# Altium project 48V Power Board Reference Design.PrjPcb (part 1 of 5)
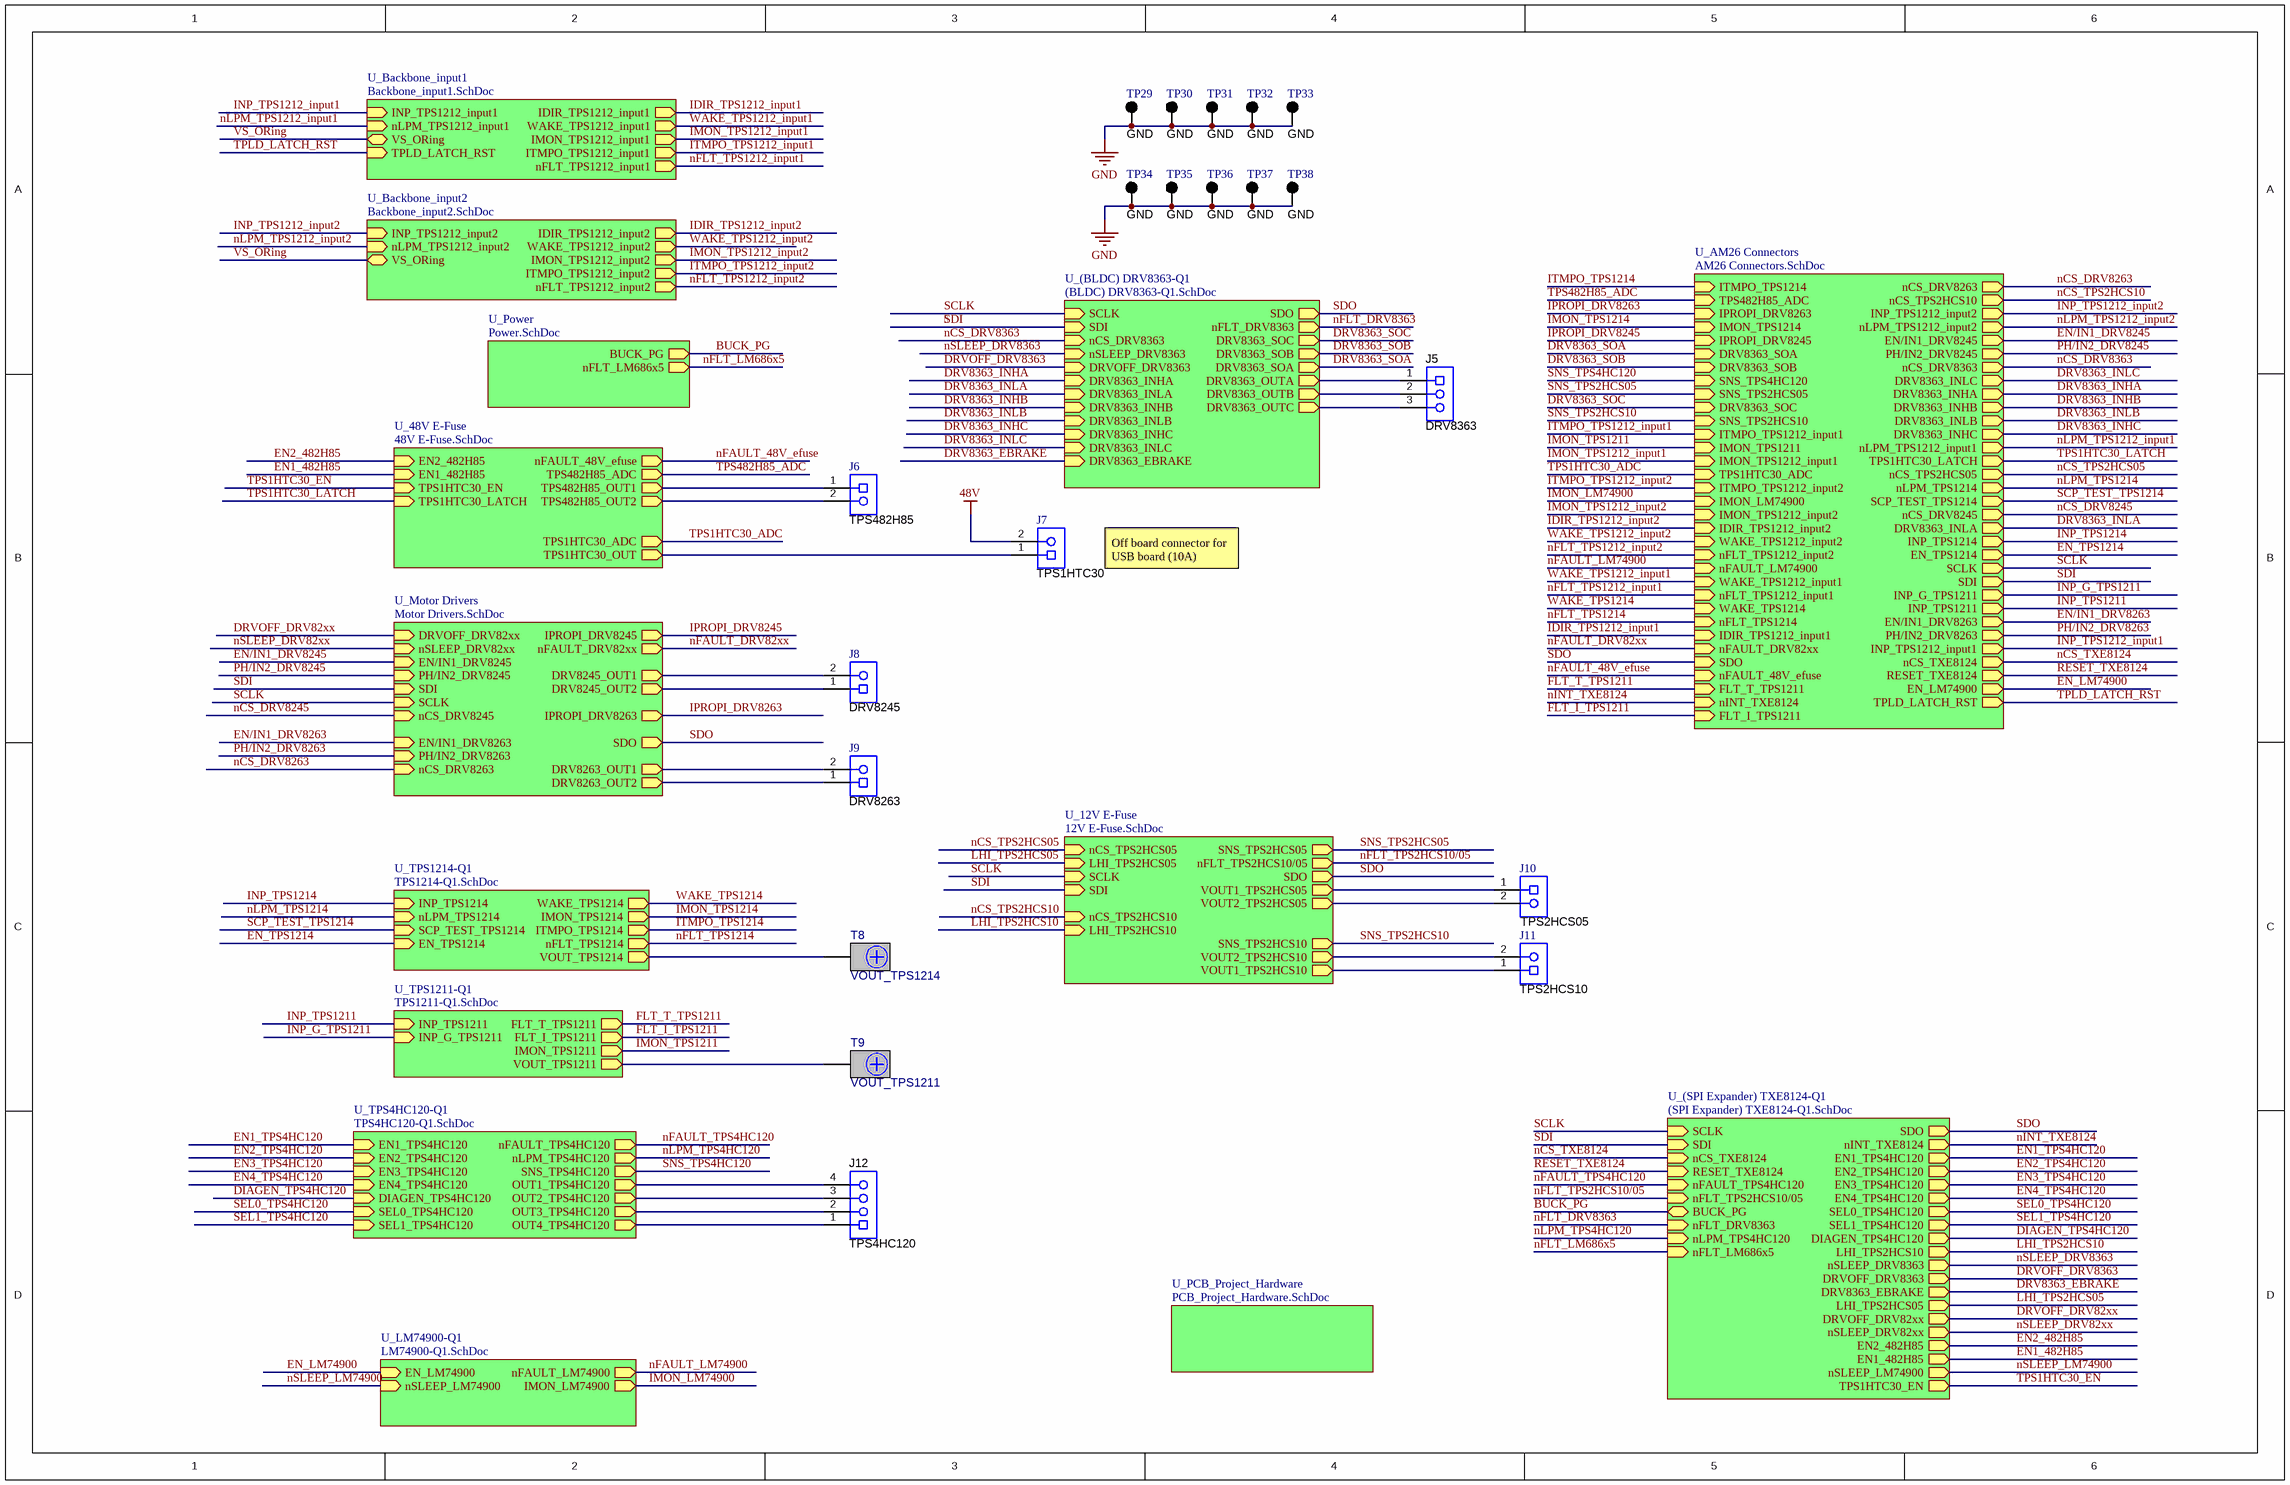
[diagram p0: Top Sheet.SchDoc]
CopyrightYear: 2025; PCB_Layout: LDN/Eagle Circuits; PCB_Rev: E3; PRJ_Customer: Public Release; PRJ_Engineer: Miguel Robertson; PRJ_Number: TIDA-020094; PRJ_Title: 48V Power Board Reference Design; SCH_Rev: E2; TechSupport: http://www.ti.com/support; TID: N/A
15 sheets, 737 parts. Net scope: hierarchical (ports join the sheet entries above them; power ports are global).
Board file: PCB_Project.PcbDoc
Sheets:
  Top Sheet.SchDoc
    U_LM74900-Q1 = LM74900-Q1.SchDoc
    U_TPS1211-Q1 = TPS1211-Q1.SchDoc
    U_TPS4HC120-Q1 = TPS4HC120-Q1.SchDoc
    U_TPS1214-Q1 = TPS1214-Q1.SchDoc
    U_PCB_Project_Hardware = PCB_Project_Hardware.SchDoc
    U_(BLDC) DRV8363-Q1 = (BLDC) DRV8363-Q1.SchDoc
    U_Motor Drivers = Motor Drivers.SchDoc
    U_12V E-Fuse = 12V E-Fuse.SchDoc
    U_Backbone_input2 = Backbone_input2.SchDoc
    U_Power = Power.SchDoc
    U_(SPI Expander) TXE8124-Q1 = (SPI Expander) TXE8124-Q1.SchDoc
    U_AM26 Connectors = AM26 Connectors.SchDoc
    U_Backbone_input1 = Backbone_input1.SchDoc
    U_48V E-Fuse = 48V E-Fuse.SchDoc

## Sheet Top Sheet.SchDoc
size 431 x 279 mm; DocumentNumber: 2; SheetNumber: 1; SheetTotal: 15

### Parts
J5  DRV8363  [Phoenix_1904150]
J6  TPS482H85  [PhoenixContact_1715721]
J7  TPS1HTC30  [PhoenixContact_1715721]
J8  DRV8245  [Phoenix_1902547]
J9  DRV8263  [Phoenix_1902547]
J10  TPS2HCS05  [Phoenix_1902547]
J11  TPS2HCS10  [PhoenixContact_1715721]
J12  TPS4HC120  [Phoenix_1715048]
T8  VOUT_TPS1214  [Panduit_CXS70-14-C]
T9  VOUT_TPS1211  [Panduit_CXS70-14-C]
TP29  GND  [Keystone5011]
TP30  GND  [Keystone5011]
TP31  GND  [Keystone5011]
TP32  GND  [Keystone5011]
TP33  GND  [Keystone5011]
TP34  GND  [Keystone5011]
TP35  GND  [Keystone5011]
TP36  GND  [Keystone5011]
TP37  GND  [Keystone5011]
TP38  GND  [Keystone5011]

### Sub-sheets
U_12V E-Fuse = 12V E-Fuse.SchDoc: VOUT1_TPS2HCS10 (out), VOUT2_TPS2HCS10 (out), LHI_TPS2HCS10 (in), nFLT_TPS2HCS10/05 (out), nCS_TPS2HCS10 (in), nCS_TPS2HCS05 (in), VOUT1_TPS2HCS05 (out), VOUT2_TPS2HCS05 (out), LHI_TPS2HCS05 (in), SCLK (in), SDI (in), SDO (out), SNS_TPS2HCS10 (out), SNS_TPS2HCS05 (out)
U_48V E-Fuse = 48V E-Fuse.SchDoc: EN2_482H85 (in), EN1_482H85 (in), TPS1HTC30_EN (in), TPS1HTC30_LATCH (in), nFAULT_48V_efuse (out), TPS1HTC30_OUT (out), TPS482H85_OUT1 (out), TPS482H85_OUT2 (out), TPS482H85_ADC (out), TPS1HTC30_ADC (out)
U_(BLDC) DRV8363-Q1 = (BLDC) DRV8363-Q1.SchDoc: SCLK (in), SDI (in), nCS_DRV8363 (in), SDO (out), nSLEEP_DRV8363 (in), DRVOFF_DRV8363 (in), nFLT_DRV8363 (out), DRV8363_INHA (in), DRV8363_INLA (in), DRV8363_INHB (in), DRV8363_INLB (in), DRV8363_INHC (in), DRV8363_INLC (in), DRV8363_SOC (out), DRV8363_SOB (out), DRV8363_SOA (out), DRV8363_EBRAKE (in), DRV8363_OUTA (out), DRV8363_OUTB (out), DRV8363_OUTC (out)
U_(SPI Expander) TXE8124-Q1 = (SPI Expander) TXE8124-Q1.SchDoc: SCLK (in), SDI (in), SDO (out), nCS_TXE8124 (in), nINT_TXE8124 (out), RESET_TXE8124 (in), EN1_TPS4HC120 (out), EN2_TPS4HC120 (out), EN3_TPS4HC120 (out), EN4_TPS4HC120 (out), SEL0_TPS4HC120 (out), SEL1_TPS4HC120 (out), nFAULT_TPS4HC120 (in), DIAGEN_TPS4HC120 (out), LHI_TPS2HCS10 (out), nFLT_TPS2HCS10/05 (in), nSLEEP_DRV8363 (out), DRVOFF_DRV8363 (out), BUCK_PG (bidir), DRV8363_EBRAKE (out), nFLT_DRV8363 (in), LHI_TPS2HCS05 (out), nLPM_TPS4HC120 (in), DRVOFF_DRV82xx (out), nSLEEP_DRV82xx (out), EN2_482H85 (out), EN1_482H85 (out), nFLT_LM686x5 (in), nSLEEP_LM74900 (out), TPS1HTC30_EN (out)
U_AM26 Connectors = AM26 Connectors.SchDoc: ITMPO_TPS1214 (in), TPS482H85_ADC (in), IPROPI_DRV8263 (in), IMON_TPS1214 (in), nCS_DRV8263 (out), IPROPI_DRV8245 (in), DRV8363_SOA (in), DRV8363_SOB (in), SNS_TPS4HC120 (in), SNS_TPS2HCS05 (in), DRV8363_SOC (in), SNS_TPS2HCS10 (in), ITMPO_TPS1212_input1 (in), IMON_TPS1211 (in), IMON_TPS1212_input1 (in), TPS1HTC30_ADC (in), ITMPO_TPS1212_input2 (in), IMON_LM74900 (in), IMON_TPS1212_input2 (in), nCS_TPS2HCS10 (out), INP_TPS1212_input2 (out), nLPM_TPS1212_input2 (out), IDIR_TPS1212_input2 (in), WAKE_TPS1212_input2 (in), nFLT_TPS1212_input2 (in), EN/IN1_DRV8245 (out), PH/IN2_DRV8245 (out), nFAULT_LM74900 (in), nCS_DRV8363 (out), DRV8363_INLC (out), DRV8363_INHA (out), DRV8363_INHB (out), DRV8363_INLB (out), DRV8363_INHC (out), WAKE_TPS1212_input1 (in), nLPM_TPS1212_input1 (out), TPS1HTC30_LATCH (out), nFLT_TPS1212_input1 (in), nCS_TPS2HCS05 (out), nLPM_TPS1214 (out), WAKE_TPS1214 (in), nFLT_TPS1214 (in), SCP_TEST_TPS1214 (out), nCS_DRV8245 (out), IDIR_TPS1212_input1 (in), nFAULT_DRV82xx (in), SDO (in), DRV8363_INLA (out), INP_TPS1214 (out), EN_TPS1214 (out), SCLK (out), SDI (out), INP_G_TPS1211 (out), INP_TPS1211 (out), EN/IN1_DRV8263 (out), PH/IN2_DRV8263 (out), nFAULT_48V_efuse (in), INP_TPS1212_input1 (out), FLT_T_TPS1211 (in), nINT_TXE8124 (in), nCS_TXE8124 (out), RESET_TXE8124 (out), FLT_I_TPS1211 (in), EN_LM74900 (out), TPLD_LATCH_RST (out)
U_Backbone_input1 = Backbone_input1.SchDoc: INP_TPS1212_input1 (in), nLPM_TPS1212_input1 (in), IDIR_TPS1212_input1 (out), WAKE_TPS1212_input1 (out), IMON_TPS1212_input1 (out), ITMPO_TPS1212_input1 (out), nFLT_TPS1212_input1 (out), VS_ORing (bidir), TPLD_LATCH_RST (in)
U_Backbone_input2 = Backbone_input2.SchDoc: INP_TPS1212_input2 (in), nLPM_TPS1212_input2 (in), IDIR_TPS1212_input2 (out), WAKE_TPS1212_input2 (out), IMON_TPS1212_input2 (out), ITMPO_TPS1212_input2 (out), nFLT_TPS1212_input2 (out), VS_ORing (bidir)
U_LM74900-Q1 = LM74900-Q1.SchDoc: nFAULT_LM74900 (out), EN_LM74900 (in), nSLEEP_LM74900 (in), IMON_LM74900 (out)
U_Motor Drivers = Motor Drivers.SchDoc: DRVOFF_DRV82xx (in), nSLEEP_DRV82xx (in), EN/IN1_DRV8245 (in), PH/IN2_DRV8245 (in), SDI (in), SCLK (in), nFAULT_DRV82xx (out), nCS_DRV8245 (in), SDO (out), EN/IN1_DRV8263 (in), PH/IN2_DRV8263 (in), nCS_DRV8263 (in), DRV8245_OUT1 (out), DRV8245_OUT2 (out), DRV8263_OUT1 (out), DRV8263_OUT2 (out), IPROPI_DRV8263 (out), IPROPI_DRV8245 (out)
U_PCB_Project_Hardware = PCB_Project_Hardware.SchDoc: no entries
U_Power = Power.SchDoc: BUCK_PG (out), nFLT_LM686x5 (out)
U_TPS4HC120-Q1 = TPS4HC120-Q1.SchDoc: EN1_TPS4HC120 (in), EN2_TPS4HC120 (in), EN3_TPS4HC120 (in), EN4_TPS4HC120 (in), DIAGEN_TPS4HC120 (in), SEL0_TPS4HC120 (in), SEL1_TPS4HC120 (in), nFAULT_TPS4HC120 (out), nLPM_TPS4HC120 (out), SNS_TPS4HC120 (out), OUT1_TPS4HC120 (out), OUT2_TPS4HC120 (out), OUT3_TPS4HC120 (out), OUT4_TPS4HC120 (out)
U_TPS1211-Q1 = TPS1211-Q1.SchDoc: INP_TPS1211 (in), INP_G_TPS1211 (in), FLT_T_TPS1211 (out), FLT_I_TPS1211 (out), IMON_TPS1211 (out), VOUT_TPS1211 (out)
U_TPS1214-Q1 = TPS1214-Q1.SchDoc: INP_TPS1214 (in), nLPM_TPS1214 (in), SCP_TEST_TPS1214 (in), WAKE_TPS1214 (out), VOUT_TPS1214 (out), IMON_TPS1214 (out), ITMPO_TPS1214 (out), nFLT_TPS1214 (out), EN_TPS1214 (in)

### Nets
48V: J7.2
GND: TP29.1 TP30.1 TP31.1 TP32.1 TP33.1 TP34.1 TP35.1 TP36.1 TP37.1 TP38.1
: sheet U_(BLDC) DRV8363-Q1/SDI, sheet U_Motor Drivers/SDI, sheet U_12V E-Fuse/SDI, sheet U_(SPI Expander) TXE8124-Q1/SDI, sheet U_AM26 Connectors/SDI  [also labelled SDI]
BUCK_PG: sheet U_Power/BUCK_PG, sheet U_(SPI Expander) TXE8124-Q1/BUCK_PG
DIAGEN_TPS4HC120: sheet U_TPS4HC120-Q1/DIAGEN_TPS4HC120, sheet U_(SPI Expander) TXE8124-Q1/DIAGEN_TPS4HC120
DRV8245_OUT1: J8.2 ; sheet U_Motor Drivers/DRV8245_OUT1
DRV8245_OUT2: J8.1 ; sheet U_Motor Drivers/DRV8245_OUT2
DRV8263_OUT1: J9.2 ; sheet U_Motor Drivers/DRV8263_OUT1
DRV8263_OUT2: J9.1 ; sheet U_Motor Drivers/DRV8263_OUT2
DRV8363_EBRAKE: sheet U_(BLDC) DRV8363-Q1/DRV8363_EBRAKE, sheet U_(SPI Expander) TXE8124-Q1/DRV8363_EBRAKE
DRV8363_INHA: sheet U_(BLDC) DRV8363-Q1/DRV8363_INHA, sheet U_AM26 Connectors/DRV8363_INHA
DRV8363_INHB: sheet U_(BLDC) DRV8363-Q1/DRV8363_INHB, sheet U_AM26 Connectors/DRV8363_INHB
DRV8363_INHC: sheet U_(BLDC) DRV8363-Q1/DRV8363_INHC, sheet U_AM26 Connectors/DRV8363_INHC
DRV8363_INLA: sheet U_(BLDC) DRV8363-Q1/DRV8363_INLA, sheet U_AM26 Connectors/DRV8363_INLA
DRV8363_INLB: sheet U_(BLDC) DRV8363-Q1/DRV8363_INLB, sheet U_AM26 Connectors/DRV8363_INLB
DRV8363_INLC: sheet U_(BLDC) DRV8363-Q1/DRV8363_INLC, sheet U_AM26 Connectors/DRV8363_INLC
DRV8363_OUTA: J5.1 ; sheet U_(BLDC) DRV8363-Q1/DRV8363_OUTA
DRV8363_OUTB: J5.2 ; sheet U_(BLDC) DRV8363-Q1/DRV8363_OUTB
DRV8363_OUTC: J5.3 ; sheet U_(BLDC) DRV8363-Q1/DRV8363_OUTC
DRV8363_SOA: sheet U_(BLDC) DRV8363-Q1/DRV8363_SOA, sheet U_AM26 Connectors/DRV8363_SOA
DRV8363_SOB: sheet U_(BLDC) DRV8363-Q1/DRV8363_SOB, sheet U_AM26 Connectors/DRV8363_SOB
DRV8363_SOC: sheet U_(BLDC) DRV8363-Q1/DRV8363_SOC, sheet U_AM26 Connectors/DRV8363_SOC
DRVOFF_DRV82xx: sheet U_Motor Drivers/DRVOFF_DRV82xx, sheet U_(SPI Expander) TXE8124-Q1/DRVOFF_DRV82xx
DRVOFF_DRV8363: sheet U_(BLDC) DRV8363-Q1/DRVOFF_DRV8363, sheet U_(SPI Expander) TXE8124-Q1/DRVOFF_DRV8363
EN1_482H85: sheet U_(SPI Expander) TXE8124-Q1/EN1_482H85, sheet U_48V E-Fuse/EN1_482H85
EN1_TPS4HC120: sheet U_TPS4HC120-Q1/EN1_TPS4HC120, sheet U_(SPI Expander) TXE8124-Q1/EN1_TPS4HC120
EN2_482H85: sheet U_(SPI Expander) TXE8124-Q1/EN2_482H85, sheet U_48V E-Fuse/EN2_482H85
EN2_TPS4HC120: sheet U_TPS4HC120-Q1/EN2_TPS4HC120, sheet U_(SPI Expander) TXE8124-Q1/EN2_TPS4HC120
EN3_TPS4HC120: sheet U_TPS4HC120-Q1/EN3_TPS4HC120, sheet U_(SPI Expander) TXE8124-Q1/EN3_TPS4HC120
EN4_TPS4HC120: sheet U_TPS4HC120-Q1/EN4_TPS4HC120, sheet U_(SPI Expander) TXE8124-Q1/EN4_TPS4HC120
EN/IN1_DRV8245: sheet U_Motor Drivers/EN/IN1_DRV8245, sheet U_AM26 Connectors/EN/IN1_DRV8245
EN/IN1_DRV8263: sheet U_Motor Drivers/EN/IN1_DRV8263, sheet U_AM26 Connectors/EN/IN1_DRV8263
EN_LM74900: sheet U_LM74900-Q1/EN_LM74900, sheet U_AM26 Connectors/EN_LM74900
EN_TPS1214: sheet U_TPS1214-Q1/EN_TPS1214, sheet U_AM26 Connectors/EN_TPS1214
FLT_I_TPS1211: sheet U_TPS1211-Q1/FLT_I_TPS1211, sheet U_AM26 Connectors/FLT_I_TPS1211
FLT_T_TPS1211: sheet U_TPS1211-Q1/FLT_T_TPS1211, sheet U_AM26 Connectors/FLT_T_TPS1211
IDIR_TPS1212_input1: sheet U_AM26 Connectors/IDIR_TPS1212_input1, sheet U_Backbone_input1/IDIR_TPS1212_input1
IDIR_TPS1212_input2: sheet U_Backbone_input2/IDIR_TPS1212_input2, sheet U_AM26 Connectors/IDIR_TPS1212_input2
IMON_LM74900: sheet U_LM74900-Q1/IMON_LM74900, sheet U_AM26 Connectors/IMON_LM74900
IMON_TPS1211: sheet U_TPS1211-Q1/IMON_TPS1211, sheet U_AM26 Connectors/IMON_TPS1211
IMON_TPS1212_input1: sheet U_AM26 Connectors/IMON_TPS1212_input1, sheet U_Backbone_input1/IMON_TPS1212_input1
IMON_TPS1212_input2: sheet U_Backbone_input2/IMON_TPS1212_input2, sheet U_AM26 Connectors/IMON_TPS1212_input2
IMON_TPS1214: sheet U_TPS1214-Q1/IMON_TPS1214, sheet U_AM26 Connectors/IMON_TPS1214
INP_G_TPS1211: sheet U_TPS1211-Q1/INP_G_TPS1211, sheet U_AM26 Connectors/INP_G_TPS1211
INP_TPS1211: sheet U_TPS1211-Q1/INP_TPS1211, sheet U_AM26 Connectors/INP_TPS1211
INP_TPS1212_input1: sheet U_AM26 Connectors/INP_TPS1212_input1, sheet U_Backbone_input1/INP_TPS1212_input1
INP_TPS1212_input2: sheet U_Backbone_input2/INP_TPS1212_input2, sheet U_AM26 Connectors/INP_TPS1212_input2
INP_TPS1214: sheet U_TPS1214-Q1/INP_TPS1214, sheet U_AM26 Connectors/INP_TPS1214
IPROPI_DRV8245: sheet U_Motor Drivers/IPROPI_DRV8245, sheet U_AM26 Connectors/IPROPI_DRV8245
IPROPI_DRV8263: sheet U_Motor Drivers/IPROPI_DRV8263, sheet U_AM26 Connectors/IPROPI_DRV8263
ITMPO_TPS1212_input1: sheet U_AM26 Connectors/ITMPO_TPS1212_input1, sheet U_Backbone_input1/ITMPO_TPS1212_input1
ITMPO_TPS1212_input2: sheet U_Backbone_input2/ITMPO_TPS1212_input2, sheet U_AM26 Connectors/ITMPO_TPS1212_input2
ITMPO_TPS1214: sheet U_TPS1214-Q1/ITMPO_TPS1214, sheet U_AM26 Connectors/ITMPO_TPS1214
LHI_TPS2HCS05: sheet U_12V E-Fuse/LHI_TPS2HCS05, sheet U_(SPI Expander) TXE8124-Q1/LHI_TPS2HCS05
LHI_TPS2HCS10: sheet U_12V E-Fuse/LHI_TPS2HCS10, sheet U_(SPI Expander) TXE8124-Q1/LHI_TPS2HCS10
nCS_DRV8245: sheet U_Motor Drivers/nCS_DRV8245, sheet U_AM26 Connectors/nCS_DRV8245
nCS_DRV8263: sheet U_Motor Drivers/nCS_DRV8263, sheet U_AM26 Connectors/nCS_DRV8263
nCS_DRV8363: sheet U_(BLDC) DRV8363-Q1/nCS_DRV8363, sheet U_AM26 Connectors/nCS_DRV8363
nCS_TPS2HCS05: sheet U_12V E-Fuse/nCS_TPS2HCS05, sheet U_AM26 Connectors/nCS_TPS2HCS05
nCS_TPS2HCS10: sheet U_12V E-Fuse/nCS_TPS2HCS10, sheet U_AM26 Connectors/nCS_TPS2HCS10
nCS_TXE8124: sheet U_(SPI Expander) TXE8124-Q1/nCS_TXE8124, sheet U_AM26 Connectors/nCS_TXE8124
nFAULT_48V_efuse: sheet U_AM26 Connectors/nFAULT_48V_efuse, sheet U_48V E-Fuse/nFAULT_48V_efuse
nFAULT_DRV82xx: sheet U_Motor Drivers/nFAULT_DRV82xx, sheet U_AM26 Connectors/nFAULT_DRV82xx
nFAULT_LM74900: sheet U_LM74900-Q1/nFAULT_LM74900, sheet U_AM26 Connectors/nFAULT_LM74900
nFAULT_TPS4HC120: sheet U_TPS4HC120-Q1/nFAULT_TPS4HC120, sheet U_(SPI Expander) TXE8124-Q1/nFAULT_TPS4HC120
nFLT_DRV8363: sheet U_(BLDC) DRV8363-Q1/nFLT_DRV8363, sheet U_(SPI Expander) TXE8124-Q1/nFLT_DRV8363  [project net nFAULT_DRV8363]
nFLT_LM686x5: sheet U_Power/nFLT_LM686x5, sheet U_(SPI Expander) TXE8124-Q1/nFLT_LM686x5
nFLT_TPS2HCS10/05: sheet U_12V E-Fuse/nFLT_TPS2HCS10/05, sheet U_(SPI Expander) TXE8124-Q1/nFLT_TPS2HCS10/05
nFLT_TPS1212_input1: sheet U_AM26 Connectors/nFLT_TPS1212_input1, sheet U_Backbone_input1/nFLT_TPS1212_input1
nFLT_TPS1212_input2: sheet U_Backbone_input2/nFLT_TPS1212_input2, sheet U_AM26 Connectors/nFLT_TPS1212_input2
nFLT_TPS1214: sheet U_TPS1214-Q1/nFLT_TPS1214, sheet U_AM26 Connectors/nFLT_TPS1214  [project net nFAULT_1214]
nINT_TXE8124: sheet U_(SPI Expander) TXE8124-Q1/nINT_TXE8124, sheet U_AM26 Connectors/nINT_TXE8124
nLPM_TPS4HC120: sheet U_TPS4HC120-Q1/nLPM_TPS4HC120, sheet U_(SPI Expander) TXE8124-Q1/nLPM_TPS4HC120
nLPM_TPS1212_input1: sheet U_AM26 Connectors/nLPM_TPS1212_input1, sheet U_Backbone_input1/nLPM_TPS1212_input1
nLPM_TPS1212_input2: sheet U_Backbone_input2/nLPM_TPS1212_input2, sheet U_AM26 Connectors/nLPM_TPS1212_input2
nLPM_TPS1214: sheet U_TPS1214-Q1/nLPM_TPS1214, sheet U_AM26 Connectors/nLPM_TPS1214
nSLEEP_DRV82xx: sheet U_Motor Drivers/nSLEEP_DRV82xx, sheet U_(SPI Expander) TXE8124-Q1/nSLEEP_DRV82xx
nSLEEP_DRV8363: sheet U_(BLDC) DRV8363-Q1/nSLEEP_DRV8363, sheet U_(SPI Expander) TXE8124-Q1/nSLEEP_DRV8363
nSLEEP_LM74900: sheet U_LM74900-Q1/nSLEEP_LM74900, sheet U_(SPI Expander) TXE8124-Q1/nSLEEP_LM74900
OUT1_TPS4HC120: J12.4 ; sheet U_TPS4HC120-Q1/OUT1_TPS4HC120
OUT2_TPS4HC120: J12.3 ; sheet U_TPS4HC120-Q1/OUT2_TPS4HC120
OUT3_TPS4HC120: J12.2 ; sheet U_TPS4HC120-Q1/OUT3_TPS4HC120
OUT4_TPS4HC120: J12.1 ; sheet U_TPS4HC120-Q1/OUT4_TPS4HC120
PH/IN2_DRV8245: sheet U_Motor Drivers/PH/IN2_DRV8245, sheet U_AM26 Connectors/PH/IN2_DRV8245
PH/IN2_DRV8263: sheet U_Motor Drivers/PH/IN2_DRV8263, sheet U_AM26 Connectors/PH/IN2_DRV8263
RESET_TXE8124: sheet U_(SPI Expander) TXE8124-Q1/RESET_TXE8124, sheet U_AM26 Connectors/RESET_TXE8124
SCLK: sheet U_(BLDC) DRV8363-Q1/SCLK, sheet U_Motor Drivers/SCLK, sheet U_12V E-Fuse/SCLK, sheet U_(SPI Expander) TXE8124-Q1/SCLK, sheet U_AM26 Connectors/SCLK
SCP_TEST_TPS1214: sheet U_TPS1214-Q1/SCP_TEST_TPS1214, sheet U_AM26 Connectors/SCP_TEST_TPS1214
SDO: sheet U_(BLDC) DRV8363-Q1/SDO, sheet U_Motor Drivers/SDO, sheet U_12V E-Fuse/SDO, sheet U_(SPI Expander) TXE8124-Q1/SDO, sheet U_AM26 Connectors/SDO
SEL0_TPS4HC120: sheet U_TPS4HC120-Q1/SEL0_TPS4HC120, sheet U_(SPI Expander) TXE8124-Q1/SEL0_TPS4HC120
SEL1_TPS4HC120: sheet U_TPS4HC120-Q1/SEL1_TPS4HC120, sheet U_(SPI Expander) TXE8124-Q1/SEL1_TPS4HC120
SNS_TPS2HCS05: sheet U_12V E-Fuse/SNS_TPS2HCS05, sheet U_AM26 Connectors/SNS_TPS2HCS05
SNS_TPS2HCS10: sheet U_12V E-Fuse/SNS_TPS2HCS10, sheet U_AM26 Connectors/SNS_TPS2HCS10
SNS_TPS4HC120: sheet U_TPS4HC120-Q1/SNS_TPS4HC120, sheet U_AM26 Connectors/SNS_TPS4HC120
TPLD_LATCH_RST: sheet U_AM26 Connectors/TPLD_LATCH_RST, sheet U_Backbone_input1/TPLD_LATCH_RST
TPS1HTC30_ADC: sheet U_AM26 Connectors/TPS1HTC30_ADC, sheet U_48V E-Fuse/TPS1HTC30_ADC
TPS1HTC30_EN: sheet U_(SPI Expander) TXE8124-Q1/TPS1HTC30_EN, sheet U_48V E-Fuse/TPS1HTC30_EN
TPS1HTC30_LATCH: sheet U_AM26 Connectors/TPS1HTC30_LATCH, sheet U_48V E-Fuse/TPS1HTC30_LATCH
TPS1HTC30_OUT: J7.1 ; sheet U_48V E-Fuse/TPS1HTC30_OUT
TPS482H85_ADC: sheet U_AM26 Connectors/TPS482H85_ADC, sheet U_48V E-Fuse/TPS482H85_ADC
TPS482H85_OUT1: J6.1 ; sheet U_48V E-Fuse/TPS482H85_OUT1
TPS482H85_OUT2: J6.2 ; sheet U_48V E-Fuse/TPS482H85_OUT2
VOUT1_TPS2HCS05: J10.1 ; sheet U_12V E-Fuse/VOUT1_TPS2HCS05
VOUT1_TPS2HCS10: J11.1 ; sheet U_12V E-Fuse/VOUT1_TPS2HCS10
VOUT2_TPS2HCS05: J10.2 ; sheet U_12V E-Fuse/VOUT2_TPS2HCS05
VOUT2_TPS2HCS10: J11.2 ; sheet U_12V E-Fuse/VOUT2_TPS2HCS10
VOUT_TPS1211: T9.1 ; sheet U_TPS1211-Q1/VOUT_TPS1211
VOUT_TPS1214: T8.1 ; sheet U_TPS1214-Q1/VOUT_TPS1214
VS_ORing: sheet U_Backbone_input2/VS_ORing, sheet U_Backbone_input1/VS_ORing
WAKE_TPS1212_input1: sheet U_AM26 Connectors/WAKE_TPS1212_input1, sheet U_Backbone_input1/WAKE_TPS1212_input1
WAKE_TPS1212_input2: sheet U_Backbone_input2/WAKE_TPS1212_input2, sheet U_AM26 Connectors/WAKE_TPS1212_input2
WAKE_TPS1214: sheet U_TPS1214-Q1/WAKE_TPS1214, sheet U_AM26 Connectors/WAKE_TPS1214

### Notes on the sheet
- Off board connector for USB board (10A)

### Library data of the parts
J5 = CMP-0055528-1: Terminal Block, 9.52mm, 3x1, R/A, TH; Manufacturer: Phoenix Contact; PartNumber: 1904150; Cert_VDE: Y; CNHeader: FALSE; Current_A: 32A; Gender: Female; Voltage_V: 1kV; Row_Count: 1; Pitch_mm: 9.52; CT: TRUE
J6 J7 J11 = CMP-0055471-1: Terminal Block, 5.08 mm, 2x1, TH; Manufacturer: Phoenix Contact; PartNumber: 1715721; Cert_VDE: Y; CNHeader: FALSE; Current_A: 17.5A; Green_Lifecycle: Not Set; Gender: Female; Cert_CULUS: N; Green_REACh: Incomplete; Voltage_V: 400V; Row_Count: 1; Pitch_mm: 5.08; ContactFinish: Tin; CT: TRUE
J8-J10 = CMP-0055527-1: Terminal Block, 9.52mm, 2x1, R/A, TH; Manufacturer: Phoenix Contact; PartNumber: 1902547; Cert_VDE: Y; CNHeader: FALSE; Current_A: 32A; Gender: Female; Voltage_V: 1kV; Row_Count: 1; Pitch_mm: 9.52; CT: TRUE
J12 = CMP-0055526-1: Terminal Block, 5mm, 4x1, R/A,TH; Manufacturer: Phoenix Contact; PartNumber: 1715048; Cert_VDE: Y; CNHeader: FALSE; Current_A: 17.5A; Gender: Female; Voltage_V: 400V; Row_Count: 1; Pitch_mm: 5; CT: TRUE
T8 T9 = CMP-0075010-2: Terminal 70A Lug; PartNumber: CXS70-14-C; Manufacturer: Panduit; CompType: Screw Terminal; CT: False; Green_Lifecycle: Not Set; Green_REACh: Incomplete
TP29-TP38 = CMP-0055148-2: Test Point, Multipurpose, Black, TH; Manufacturer: Keystone Electronics; CNHeader: FALSE; ContactFinish: Silver; Green_REACh: Passed; Green_Lifecycle: Active; CT: TRUE

## Sheet LM74900-Q1.SchDoc
size 431 x 279 mm; Date: Not shown in title block; ApprovedBy: Not shown in title block; CheckedBy: Not shown in title block; Author: Not shown in title block; CompanyName: Not shown in title block; Engineer: Not shown in title block; Organization: Not shown in title block; Address1: Not shown in title block; Address2: Not shown in title block; Address3: Not shown in title block; Address4: Not shown in title block; DocumentNumber: 6; Revision: Use project parameter SCH_Rev; SheetNumber: 11; SheetTotal: 15; PageSetup: Record=PageOptions¦CenterHorizontal=True¦CenterVertical=True¦PrintScale=1.00¦XCorrection=1.00¦YCorrection=1.00¦PrintKind=0¦BorderSize=5000000¦LeftOffset=0¦BottomOffset=0¦Orientation=2¦PaperLength=1000¦PaperWidth=1000¦Scale=100¦PaperSource=15¦PrintQuality=600¦MediaType=1¦DitherType=10¦PaperKind=Letter¦PrintScaleMode=1
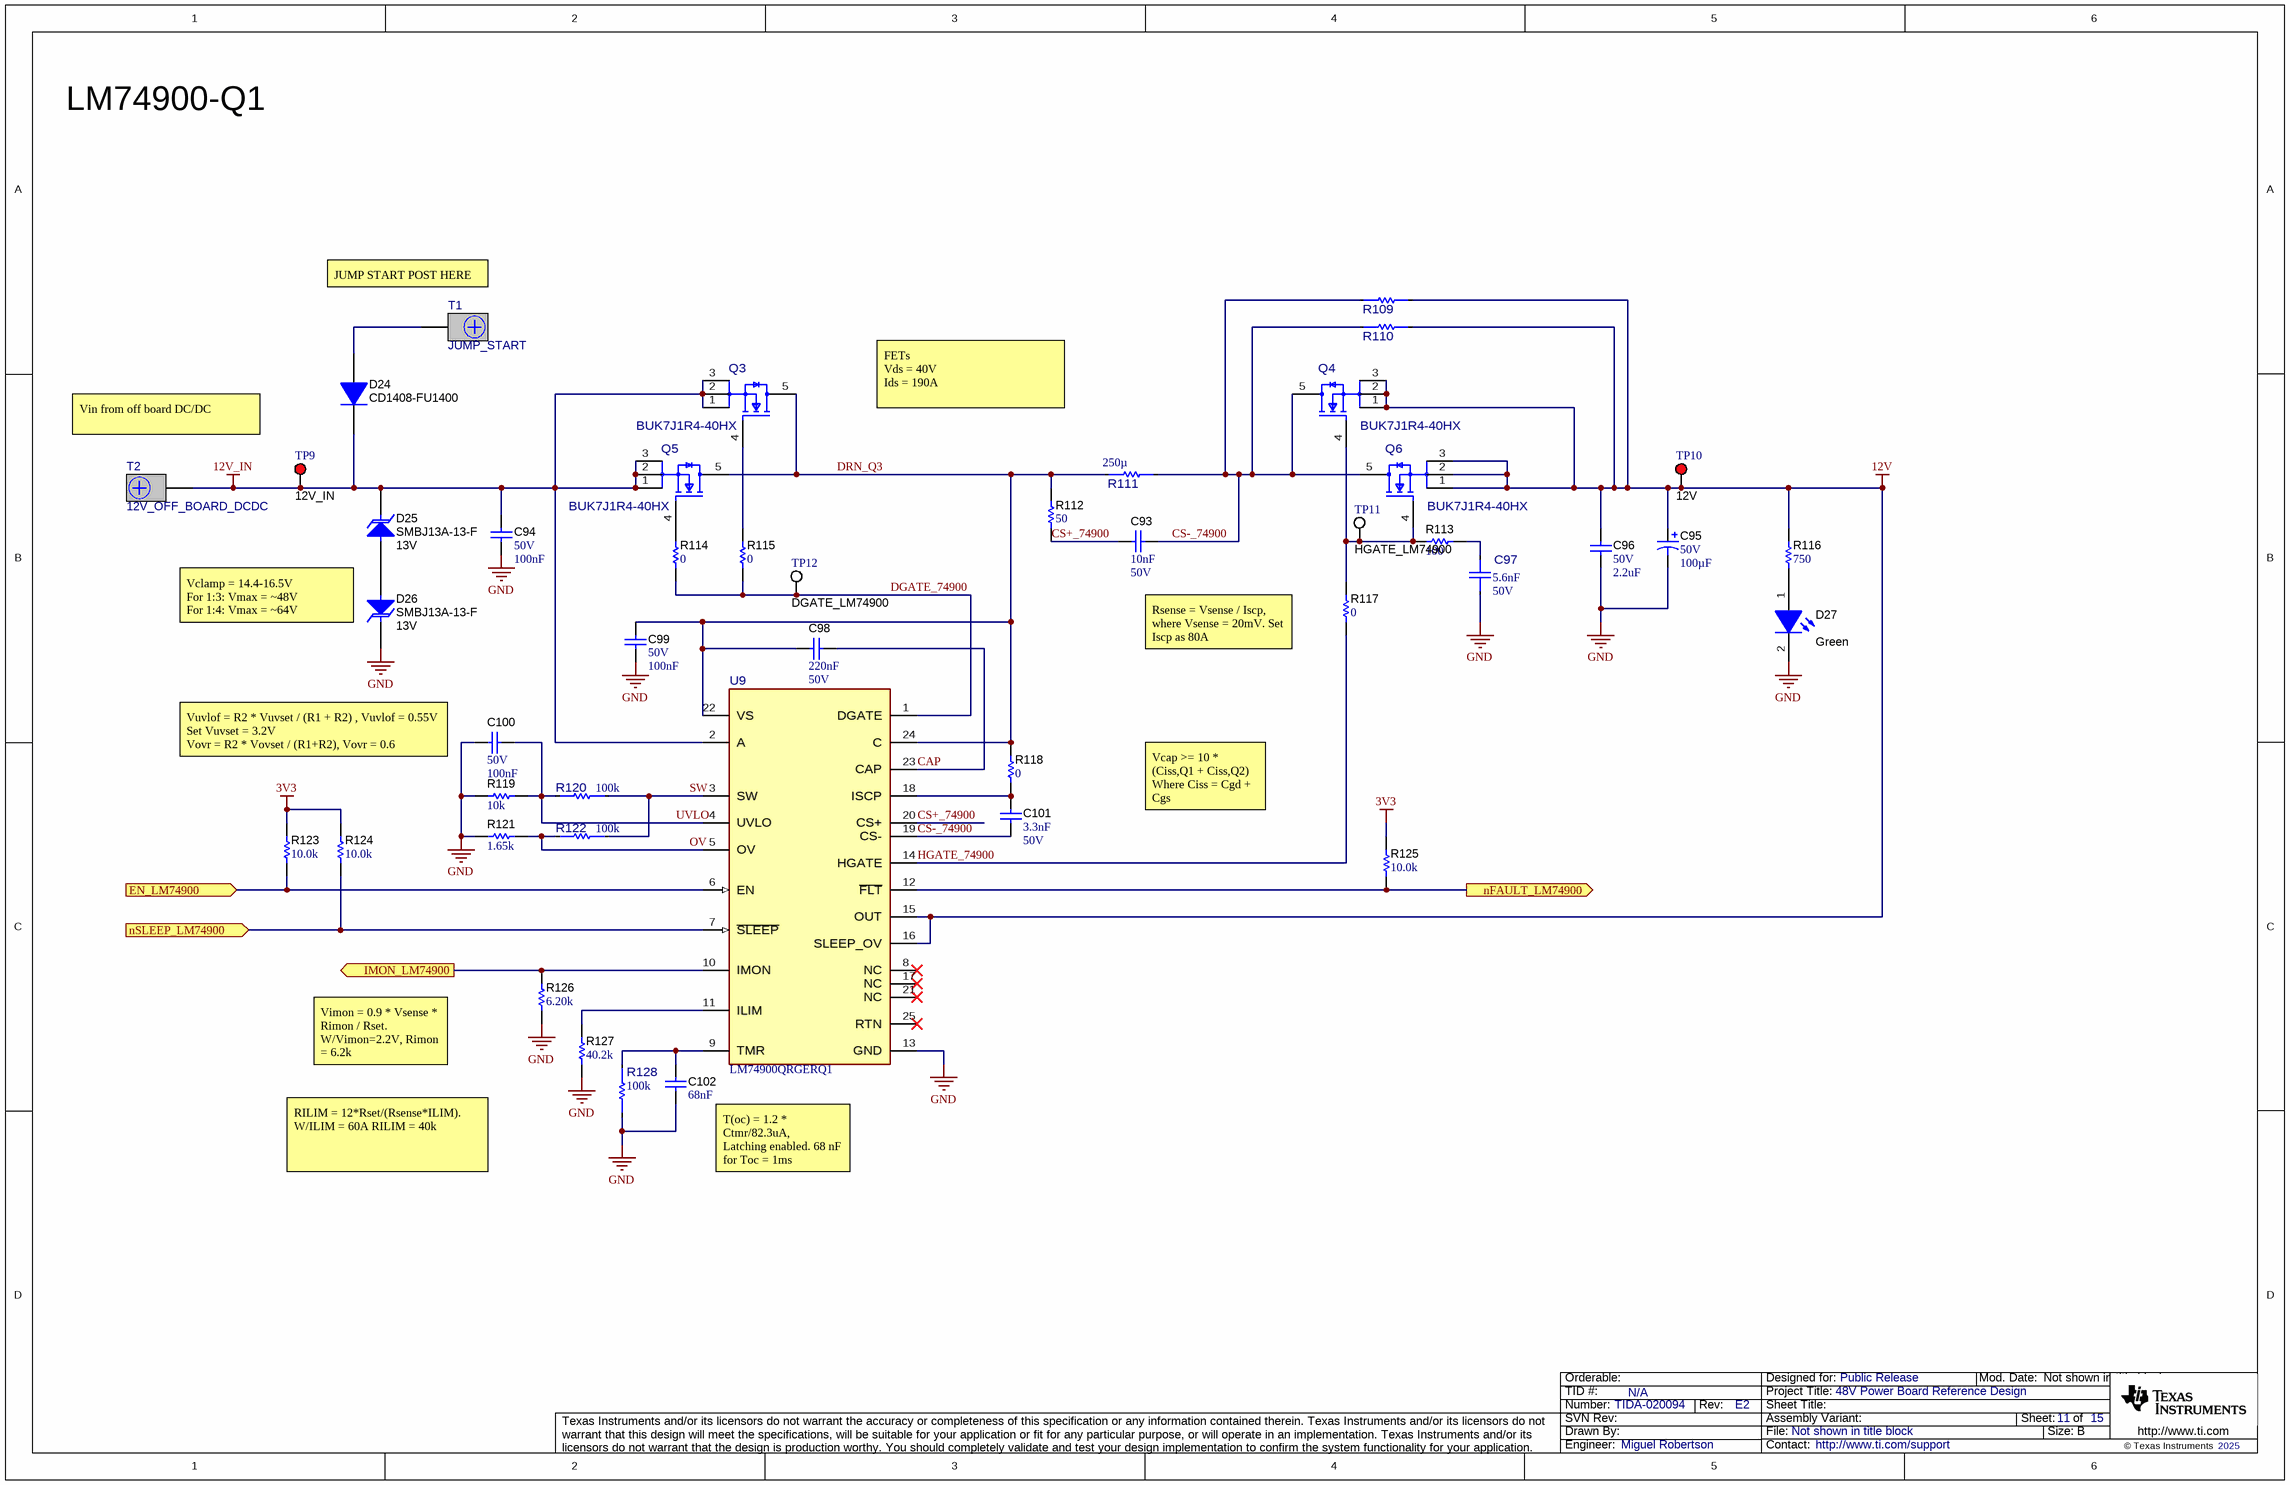
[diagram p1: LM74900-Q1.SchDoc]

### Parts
C93  Cap_F: 10nF  VDC_V: 50V  [0603]  (hidden comment: C0603C103J5RACTU)
C94  VDC_V: 50V  Cap_F: 100nF  [0603L]  (hidden comment: 06035C104K4Z4A)
C95  VDC_V: 50V  ValueDisplayed: 100µF  [Panasonic_SMT_800x1020]  (hidden comment: EEEFP1H101AP)
C96  VDC_V: 50V  ValueDisplayed: 2.2uF  [0603]  (hidden comment: GRM188R61H225KE11D)
C97  ValueDisplayed: 5.6nF  VDC_V: 50V  [FP-CL10B562KB8NNNC_0603-IPC_C]  (hidden comment: CL10B562KB8NNNC)
C98  Cap_F: 220nF  VDC_V: 50V  [0603]  (hidden comment: CGA3E3X7R1H224K080AB)
C99  VDC_V: 50V  Cap_F: 100nF  [0603L]  (hidden comment: 06035C104K4Z4A)
C100  VDC_V: 50V  Cap_F: 100nF  [0603L]  (hidden comment: 06035C104K4Z4A)
C101  Cap_F: 3.3nF  VDC_V: 50V  [0603]  (hidden comment: C0603C332K5RACTU)
C102  Cap_F: 68nF  [0603]  (hidden comment: 06035C104KAZ2A)
D24  CD1408-FU1400  [Diode_1408]
D25  SMBJ13A-13-F  value 13V  [SMB]
D26  SMBJ13A-13-F  value 13V  [SMB]
D27  value Green  [LTST-C191_Green]  (hidden comment: LTST-C191KGKT)
Q3  BUK7J1R4-40HX  [FP-BUK7J1R4-40HX_LFPAK56E-MFG]
Q4  BUK7J1R4-40HX  [FP-BUK7J1R4-40HX_LFPAK56E-MFG]
Q5  BUK7J1R4-40HX  [FP-BUK7J1R4-40HX_LFPAK56E-MFG]
Q6  BUK7J1R4-40HX  [FP-BUK7J1R4-40HX_LFPAK56E-MFG]
R109  CSS2H-2512R-L500F  [FP-CSS2H-2512R-L500F_2512-MFG]  (value not drawn)
R110  CSS2H-2512R-L500F  [FP-CSS2H-2512R-L500F_2512-MFG]  (value not drawn)
R111  value 250µ  [FP-HoLRS2512_2512-MFG]  (hidden comment: HoLRS2512-0.25mR-1%)
R112  ValueDisplayed: 50  [0603]  (hidden comment: CRCW060350R0FKEA)
R113  ValueDisplayed: 100  [0603]  (hidden comment: ERJ-3GEY0R00V)
R114  ValueDisplayed: 0  [0603]  (hidden comment: ERJ-3GEY0R00V)
R115  ValueDisplayed: 0  [0603]  (hidden comment: ERJ-3GEY0R00V)
R116  ValueDisplayed: 750  [0603]  (hidden comment: RC0603FR-07750RL)
R117  ValueDisplayed: 0  [0603]  (hidden comment: CRCW06030000Z0EA)
R118  ValueDisplayed: 0  [0603]  (hidden comment: CRCW060350R0FKEA)
R119  ValueDisplayed: 10k  [0603]  (hidden comment: RT0603BRD0720K8L)
R120  value 100k  [FP-ERJ-PB3B1003V_0603-IPC_A]  (hidden comment: ERJ-PB3B1003V)
R121  ValueDisplayed: 1.65k  [0603]  (hidden comment: RT0603BRD071K62L)
R122  value 100k  [FP-ERJ-PB3B1003V_0603-IPC_A]  (hidden comment: ERJ-PB3B1003V)
R123  ValueDisplayed: 10.0k  [0603]  (hidden comment: ERJ-3EKF1002V)
R124  ValueDisplayed: 10.0k  [0603]  (hidden comment: ERJ-3EKF1002V)
R125  ValueDisplayed: 10.0k  [0603]  (hidden comment: ERJ-3EKF1002V)
R126  ValueDisplayed: 6.20k  [0603]  (hidden comment: RC0603FR-076K2L)
R127  ValueDisplayed: 40.2k  [0603]  (hidden comment: RC0603FR-0740K2L)
R128  value 100k  [FP-ERJ-PB3B1003V_0603-IPC_A]  (hidden comment: ERJ-PB3B1003V)
T1  JUMP_START  [Panduit_CXS70-14-C]
T2  12V_OFF_BOARD_DCDC  [Panduit_CXS70-14-C]
TP9  12V_IN  [Keystone5010]
TP10  12V  [Keystone5010]
TP11  HGATE_LM74900  [Keystone5012]
TP12  DGATE_LM74900  [Keystone5012]
U9  LM74900QRGERQ1  [RGE0024T-MFG]

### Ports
EN_LM74900 (in), IMON_LM74900 (out), nFAULT_LM74900 (out), nSLEEP_LM74900 (in)

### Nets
3V3: R123.2 R124.2 R125.2
12V: C95.1(+) C96.1 Q4.1(S) Q4.2(S) Q4.3(S) Q6.1(S) Q6.2(S) Q6.3(S) R109.2 R110.2 R116.2 TP10.1 U9.15(OUT) U9.16(SLEEP_OV)
12V_IN: C94.2 D24.1(K) D25.1(K) Q3.1(S) Q3.2(S) Q3.3(S) Q5.1(S) Q5.2(S) Q5.3(S) T2.1 TP9.1 U9.2(A)
GND: C94.1 C95.2(-) C96.2 C97.1 C99.1 C100.1 C102.2 D26.1(K) D27.2(K) R119.1 R121.1 R126.1 R127.1 R128.2 U9.13(GND)
CAP: C98.1 U9.23(CAP)  [project net CAP_11]
CS+_74900: C93.2 R112.1 U9.20(CS+)  [project net CS+_74900_11]
CS-_74900: C93.1 C101.2 Q4.5(D) Q6.5(D) R109.1 R110.1 R111.2 U9.19(CS-)  [project net CS-_74900_11]
DGATE_74900: R114.1 R115.1 TP12.1 U9.1(DGATE)  [project net DGATE_74900_11]
DRN_Q3: C98.2 C99.2 Q3.5(D) Q5.5(D) R111.1 R112.2 R118.2 U9.22(VS) U9.24(C)  [project net DRN_Q3_11]
EN_LM74900: R123.1 U9.6(EN) ; port EN_LM74900
HGATE_74900: R117.1 U9.14(HGATE)  [project net HGATE_74900_11]
IMON_LM74900: R126.2 U9.10(IMON) ; port IMON_LM74900
nFAULT_LM74900: R125.1 U9.12(~{FLT}) ; port nFAULT_LM74900
nSLEEP_LM74900: R124.1 U9.7(~{SLEEP}) ; port nSLEEP_LM74900
OV: R121.2 R122.2 U9.5(OV)  [project net OV_11]
SW: R120.1 R122.1 U9.3(SW)  [project net SW_11]
UVLO: C100.2 R119.2 R120.2 U9.4(UVLO)  [project net UVLO_11]
NetC97_2: C97.2 R113.2
NetC101_1: C101.1 R118.1 U9.18(ISCP)
NetC102_1: C102.1 R128.1 U9.9(TMR)
NetD24_2: D24.2(A) T1.1
NetD25_2: D25.2(A) D26.2(A)
NetD27_1: D27.1(A) R116.1
NetQ3_4: Q3.4(G) R115.2
NetQ4_4: Q4.4(G) Q6.4(G) R113.1 R117.2 TP11.1
NetQ5_4: Q5.4(G) R114.2
NetR127_2: R127.2 U9.11(ILIM)

Not connected (* = marked no-connect by the designer): U9 8(NC)* 17(NC)* 21(NC)* 25(RTN)*

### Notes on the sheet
- LM74900-Q1
- (near T1) JUMP START POST HERE
- Vin from off board DC/DC
- FETs
  Vds = 40V
  Ids = 190A
- Vclamp = 14.4-16.5V
  For 1:3: Vmax = ~48V
  For 1:4: Vmax = ~64V
- Rsense = Vsense / Iscp, where Vsense = 20mV. Set Iscp as 80A
- Vuvlof = R2 * Vuvset / (R1 + R2) , Vuvlof = 0.55V
  Set Vuvset = 3.2V
  Vovr = R2 * Vovset / (R1+R2), Vovr = 0.6
- Vcap >= 10 * (Ciss,Q1 + Ciss,Q2)
  Where Ciss = Cgd + Cgs
- Vimon = 0.9 * Vsense * Rimon / Rset. W/Vimon=2.2V, Rimon = 6.2k
- RILIM = 12*Rset/(Rsense*ILIM). W/ILIM = 60A RILIM = 40k
- T(oc) = 1.2 * Ctmr/82.3uA,
  Latching enabled. 68 nF for Toc = 1ms

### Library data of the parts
C93 = CMP-0006850-4: CAP, CERM, 0.01 uF, 50 V, +/- 5%, X7R, 0603; Manufacturer: Kemet; TaMin_C: -55°C; Polarized: N; SizeAreaWB_mm2: 4.68; Value1: Unknown; U/M: EA; Value: 0.01uF; TaMax_C: 125°C; SizeZ_mm: 1; SizeX_mm: 1.6; SizeY_mm: 0.8; SizeArea_mm2: 1.28; AEC Category: Q200
C94 C99 C100 = CMP-0084736-1: CAP, CERM, 0.1 µF, 50 V,+/- 10%, X7R, AEC-Q200 Grade 0, 0603; Manufacturer: AVX; SizeX_mm: 1.6; AEC Qualified: Y; Value: 0.1uF; TaMin_C: -55°C; TaMax_C: 125°C; SizeY_mm: 0.8; SizeAreaWB_mm2: 4.68; AEC Grade: 0; SizeArea_mm2: 1.28; SizeZ_mm: 1; ValueDisplayed: 0.1µF; U/M: EA; Cap_Case: 0603; Polarized: N; AEC Category: Q200
C95 = CMP-0077295-1: CAP, AL, 100 µF, 50 V, +/- 20%, 0.18 ohm, AEC-Q200 Grade 2, SMD; Manufacturer: Panasonic; IRMS_A: 670mA; SizeAreaWB_mm2: 106.09; SizeArea_mm2: 68.89; AEC Qualified: Y; AEC Category: Q200; Value: 100uF; TaMax_C: 105°C; SizeZ_mm: 10.5; AEC Grade: 2; TaMin_C: -55°C; SizeY_mm: 8.3; U/M: EA; CompType: Capacitor; ESR_ohm: 0.18; Cap_Case: 8x10.2mm
C96 = CMP-0007353-5: CAP, CERM, 2.2 uF, 50 V, +/- 10%, X5R, 0603; Manufacturer: MuRata; TaMin_C: -55°C; Polarized: N; SizeAreaWB_mm2: 4.68; Value1: Unknown; U/M: EA; Value: 2.2uF; TaMax_C: 85°C; SizeZ_mm: 1; SizeX_mm: 1.6; SizeY_mm: 0.8; SizeArea_mm2: 1.28; Cap_F: 2.2µF; AEC Category: Q200
C97 = CMP-0093561-1: Cap Ceramic 5.6nF 50V X7R ±10% Pad SMD 0603 +125°C T/R; Manufacturer: Samsung; AEC Qualified: No; SizeZ_mm: 0.9mm; TempCo: 0.15
C98 = CMP-0007094-5: CAP, CERM, 0.22 uF, 50 V, +/- 10%, X7R, AEC-Q200 Grade 1, 0603; Manufacturer: TDK; TaMin_C: -55°C; ESR_ohm: 21.699m; Polarized: N; SizeAreaWB_mm2: 4.68; Value1: 0.021699 ohm; U/M: EA; Value: 0.22uF; TaMax_C: 125°C; SizeZ_mm: 1; SizeX_mm: 1.6; SizeY_mm: 0.8; SizeArea_mm2: 1.28; AEC Qualified: Y; IRMS_A: 1.125A; AEC Category: Q200
C101 = CMP-0006922-4: CAP, CERM, 3300 pF, 50 V, +/- 10%, X7R, 0603; Manufacturer: Kemet; TaMin_C: -55°C; Polarized: N; SizeAreaWB_mm2: 4.68; Value1: Unknown; U/M: EA; Value: 3300pF; TaMax_C: 125°C; SizeZ_mm: 1; SizeX_mm: 1.6; SizeY_mm: 0.8; SizeArea_mm2: 1.28; AEC Category: Q200
C102 = CMP-0079095-1: CAP, CERM, 0.1 µF, 50 V,+/- 10%, X7R, AEC-Q200 Grade 1, 0603; Manufacturer: AVX; SizeAreaWB_mm2: 4.68; SizeArea_mm2: 1.28; AEC Qualified: Y; AEC Category: Q200; Value: 0.1uF; TaMax_C: 125°C; SizeZ_mm: 1; Polarized: N; TaMin_C: -55°C; VDC_V: 50V; SizeY_mm: 0.8; U/M: EA; SizeX_mm: 1.6; ValueDisplayed: 0.1µF
D24 = CMP-0029014-2: Diode, Ultrafast, 400 V, 1 A, 1408 Diode; Manufacturer: Bourns; SizeAreaWB_mm2: 12.76; SizeZ_mm: 1.15; Value2: 1.05V; Green_REACh: Incomplete; SizeY_mm: 1.9; Value: 400V; TJmax_C: 150°C; Io_A: 1A; AEC Category: Q101; RJC_CperW: 40; SizeX_mm: 3.4; SizeArea_mm2: 6.46; Green_Lifecycle: Not Set
D25 D26 = CMP-0005541-4: Diode, TVS, Uni, 13 V, 21.5 Vc, SMB; Manufacturer: Diodes Inc.; SizeArea_mm2: 21.336; SizeAreaWB_mm2: 44.156; Value1: 600W; Vbr_Min: 14.4V; Ipp: 27.9A; SizeZ_mm: 2.6; Vbr_Max: 16.5V; Vc: 21.5V; AEC Category: Q101; SizeY_mm: 3.81; SizeX_mm: 5.6
D27 = CMP-0078478-1: LED, Green, SMD; Manufacturer: Lite-On; Io_A: 30mA; Power_TotalModule: 75mW; Green_Lifecycle: Not Set; Vr_V: 5V; Tjmax_C: 85°C; Green_REACh: Incomplete; Value1: 0.075W; Angle: 130; Ir_A: 10µA; Vf_V: 2V; Type: AlInGaP
Q3-Q6 = CMP-0098150-1: Trans MOSFET N-CH 40V 190A Automotive 5-Pin(4+Tab) LFPAK T/R; Manufacturer: Nexperia; Drain To Source Breakdown Voltage: 42V; Threshold Vgs Max: 3.6V; Turn On Delay Time: 19ns; ChMode: False; Standoff Height: 0mm; Rdson45_ohm: 1.06m; Power_W: 395W; TJmax_C: +175°C; Pulse Drain Current: 600A; QgTyp_nC: 73nC @ 10V; Vgs_V: 20V; AEC Grade: Grade 0; AEC Qualified: Yes; Turn Off Delay Time: 43ns; VdsMax_V: 1.2V; Input Capacitace At Vds: 5436pF @ 25V; Number Of Channels: 1; SizeZ_mm: 1.25mm; Reverse Recovery Charge: 39nC; Reverse Recovery Time: 37ns; Typ Forward Diode Voltage: 0.8V; Threshold Vgs Min: 2.4V
R109 R110 = CMP-0095938-1: 500 µOhms ±1% 6W Chip Resistor 2512 (6432 Metric) Automotive AEC-Q200, Current Sense Metal Element; Manufacturer: Bourns; AEC Qualified: Yes; Standoff Height: 0.15mm; SizeZ_mm: 1.23mm; Value: 500µ; TempCo: 100ppm/°C; AEC Grade: Grade 0
R111 = CMP-0124268-3: 0.25 mOhms ±1% 3W Chip Resistor 2512 (6332 Metric) Automotive AEC-Q200, Current Sense Metal Element; Manufacturer: Shenzhen Milliohm Electronic; AEC Grade: Grade 0; AEC Qualified: Yes; SizeZ_mm: 1.9mm; TempCo: 50ppm/°C
R112 = CMP-0022479-4: RES, 50, 1%, 0.1 W, AEC-Q200 Grade 0, 0603; Manufacturer: Vishay-Dale; Power_W: 100mW; TempCo: 100 ppm/C; Value_Code: 50R0; Value: 50; SizeX_mm: 1.6; SizeY_mm: 0.8; SizeZ_mm: 1; Value2: 0.1W; SizeArea_mm2: 1.28; AEC Qualified: Y; VDC_V: 75V; AEC Category: Q200; AEC Grade: 0
R113-R115 = CMP-0025874-4: RES, 0, 5%, 0.1 W, AEC-Q200 Grade 0, 0603; Manufacturer: Panasonic; Power_W: 100mW; TempCo: 600 ppm/C; Value_Code: 0000; Value: 0; EIA_Code: E24; SizeX_mm: 1.6; SizeY_mm: 0.8; SizeZ_mm: 1; Value2: 0.1W; SizeArea_mm2: 1.28; AEC Qualified: Y; VDC_V: 50V; AEC Category: Q200; SizeAreaWB_mm2: 4.68
R116 = CMP-0023266-5: RES, 750, 1%, 0.1 W, 0603; Manufacturer: Yageo; Power_W: 100mW; TempCo: 100 ppm/C; Value_Code: 750R; Value: 750; EIA_Code: E96; SizeX_mm: 1.6; SizeY_mm: 0.8; SizeZ_mm: 1; Value2: 0.1W; SizeArea_mm2: 1.28; AEC Qualified: N; VDC_V: 75V; AEC Category: Q200; SizeAreaWB_mm2: 4.68
R117 = CMP-0025697-4: RES, 0, 5%, 0.1 W, AEC-Q200 Grade 0, 0603; Manufacturer: Vishay-Dale; Power_W: 100mW; TempCo: 200 ppm/C; Value_Code: 0000; Value: 0; EIA_Code: E24; SizeX_mm: 1.6; SizeY_mm: 0.8; SizeZ_mm: 1; Value2: 0.1W; SizeArea_mm2: 1.28; CompType: Resistor; AEC Qualified: Y; VDC_V: 75V; AEC Category: Q200
R118 = CMP-0022479-4: RES, 50, 1%, 0.1 W, AEC-Q200 Grade 0, 0603; Manufacturer: Vishay-Dale; Power_W: 100mW; TempCo: 100 ppm/C; Value_Code: 50R0; Value: 50; SizeX_mm: 1.6; SizeY_mm: 0.8; SizeZ_mm: 1; Value2: 0.1W; SizeArea_mm2: 1.28; AEC Qualified: Y; VDC_V: 75V; AEC Category: Q200
R119 = CMP-0023930-3: RES, 20.8 k, 0.1%, 0.1 W, 0603; Manufacturer: Yageo America; Power_W: 100mW; TempCo: 25 ppm/C; Value_Code: 20k8; U/M: EA; Value: 20.8k; EIA_Code: E192; SizeX_mm: 1.6; SizeY_mm: 0.8; SizeZ_mm: 1; Value2: 0.1W; SizeArea_mm2: 1.28; VDC_V: 75V; AEC Category: Q200
R120 R122 R128 = CMP-0092407-1: Res Thick Film 0603 100K Ohm 0.1% 0.2W(1/5W) ±50ppm/°C Pad SMD Automotive T/R; Manufacturer: Panasonic; Power_W: 200mW; VDC_V: 150V; AEC Qualified: Yes; SizeZ_mm: 0.55mm; AEC Grade: Grade 0
R121 = CMP-0023900-3: RES, 1.62 k, 0.1%, 0.1 W, 0603; Manufacturer: Yageo America; Power_W: 100mW; TempCo: 25 ppm/C; Value_Code: 1k62; U/M: EA; Value: 1.62k; EIA_Code: E192; SizeX_mm: 1.6; SizeY_mm: 0.8; SizeZ_mm: 1; Value2: 0.1W; SizeArea_mm2: 1.28; VDC_V: 75V; AEC Category: Q200
R123-R125 = CMP-0022684-3: RES, 10.0 k, 1%, 0.1 W, 0603; Manufacturer: Panasonic; Power_W: 100mW; TempCo: 100 ppm/C; Value_Code: 10k0; U/M: EA; Value: 10.0k; EIA_Code: E96; Res_ohm: 10k; SizeX_mm: 1.6; SizeY_mm: 0.8; SizeZ_mm: 1; Value2: 0.1W; SizeArea_mm2: 1.28; VDC_V: 75V; AEC Category: Q200
R126 = CMP-0023248-5: RES, 6.20 k, 1%, 0.1 W, 0603; Manufacturer: Yageo; Power_W: 100mW; TempCo: 100 ppm/C; Value_Code: 6k20; Value: 6.20k; Res_ohm: 6.2k; SizeX_mm: 1.6; SizeY_mm: 0.8; SizeZ_mm: 1; Value2: 0.1W; SizeArea_mm2: 1.28; AEC Qualified: N; VDC_V: 75V; AEC Category: Q200; SizeAreaWB_mm2: 4.68
R127 = CMP-0023098-5: RES, 40.2 k, 1%, 0.1 W, 0603; Manufacturer: Yageo; Power_W: 100mW; TempCo: 100 ppm/C; Value_Code: 40k2; Value: 40.2k; EIA_Code: E96; SizeX_mm: 1.6; SizeY_mm: 0.8; SizeZ_mm: 1; Value2: 0.1W; SizeArea_mm2: 1.28; AEC Qualified: N; VDC_V: 75V; AEC Category: Q200; SizeAreaWB_mm2: 4.68
T1 T2 = CMP-0075010-2: as T8 on sheet Top Sheet
TP9 TP10 = CMP-0055147-2: Test Point, Multipurpose, Red, TH; Manufacturer: Keystone Electronics; CT: TRUE; ContactFinish: Silver; Green_Lifecycle: Active; CNHeader: FALSE; Green_REACh: Passed
TP11 TP12 = CMP-0055149-1: Test Point, Multipurpose, White, TH; Manufacturer: Keystone; CNHeader: FALSE; Green_Lifecycle: Active; Green_REACh: Passed; ContactFinish: Silver; CT: TRUE
U9 = CMP-0122616-1: Automotive ideal diode with circuit breaker, under- and overvoltage protection with fault output 24-VQFN -40 to 125; Manufacturer: Texas Instruments; SizeZ_mm: 1mm; AEC Qualified: Yes; AEC Grade: Grade 1; Max Supply Voltage: 65V; Min Supply Voltage: 3V; Nominal Supply Current: 630-635uA; Number Of Outputs: 1; Standoff Height: 0mm; TaMax_C: +125°C; TaMin_C: -40°C; TJmax_C: +150°C

## Sheet TPS1211-Q1.SchDoc
size 431 x 279 mm; Date: Not shown in title block; ApprovedBy: Not shown in title block; CheckedBy: Not shown in title block; Author: Not shown in title block; CompanyName: Not shown in title block; Engineer: Not shown in title block; Organization: Not shown in title block; Address1: Not shown in title block; Address2: Not shown in title block; Address3: Not shown in title block; Address4: Not shown in title block; DocumentNumber: 11; Revision: Use project parameter SCH_Rev; SheetNumber: 8; SheetTotal: 15; PageSetup: Record=PageOptions¦CenterHorizontal=True¦CenterVertical=True¦PrintScale=1.00¦XCorrection=1.00¦YCorrection=1.00¦PrintKind=0¦BorderSize=5000000¦LeftOffset=0¦BottomOffset=0¦Orientation=2¦PaperLength=1000¦PaperWidth=1000¦Scale=100¦PaperSource=15¦PrintQuality=600¦MediaType=1¦DitherType=10¦PaperKind=Letter¦PrintScaleMode=1
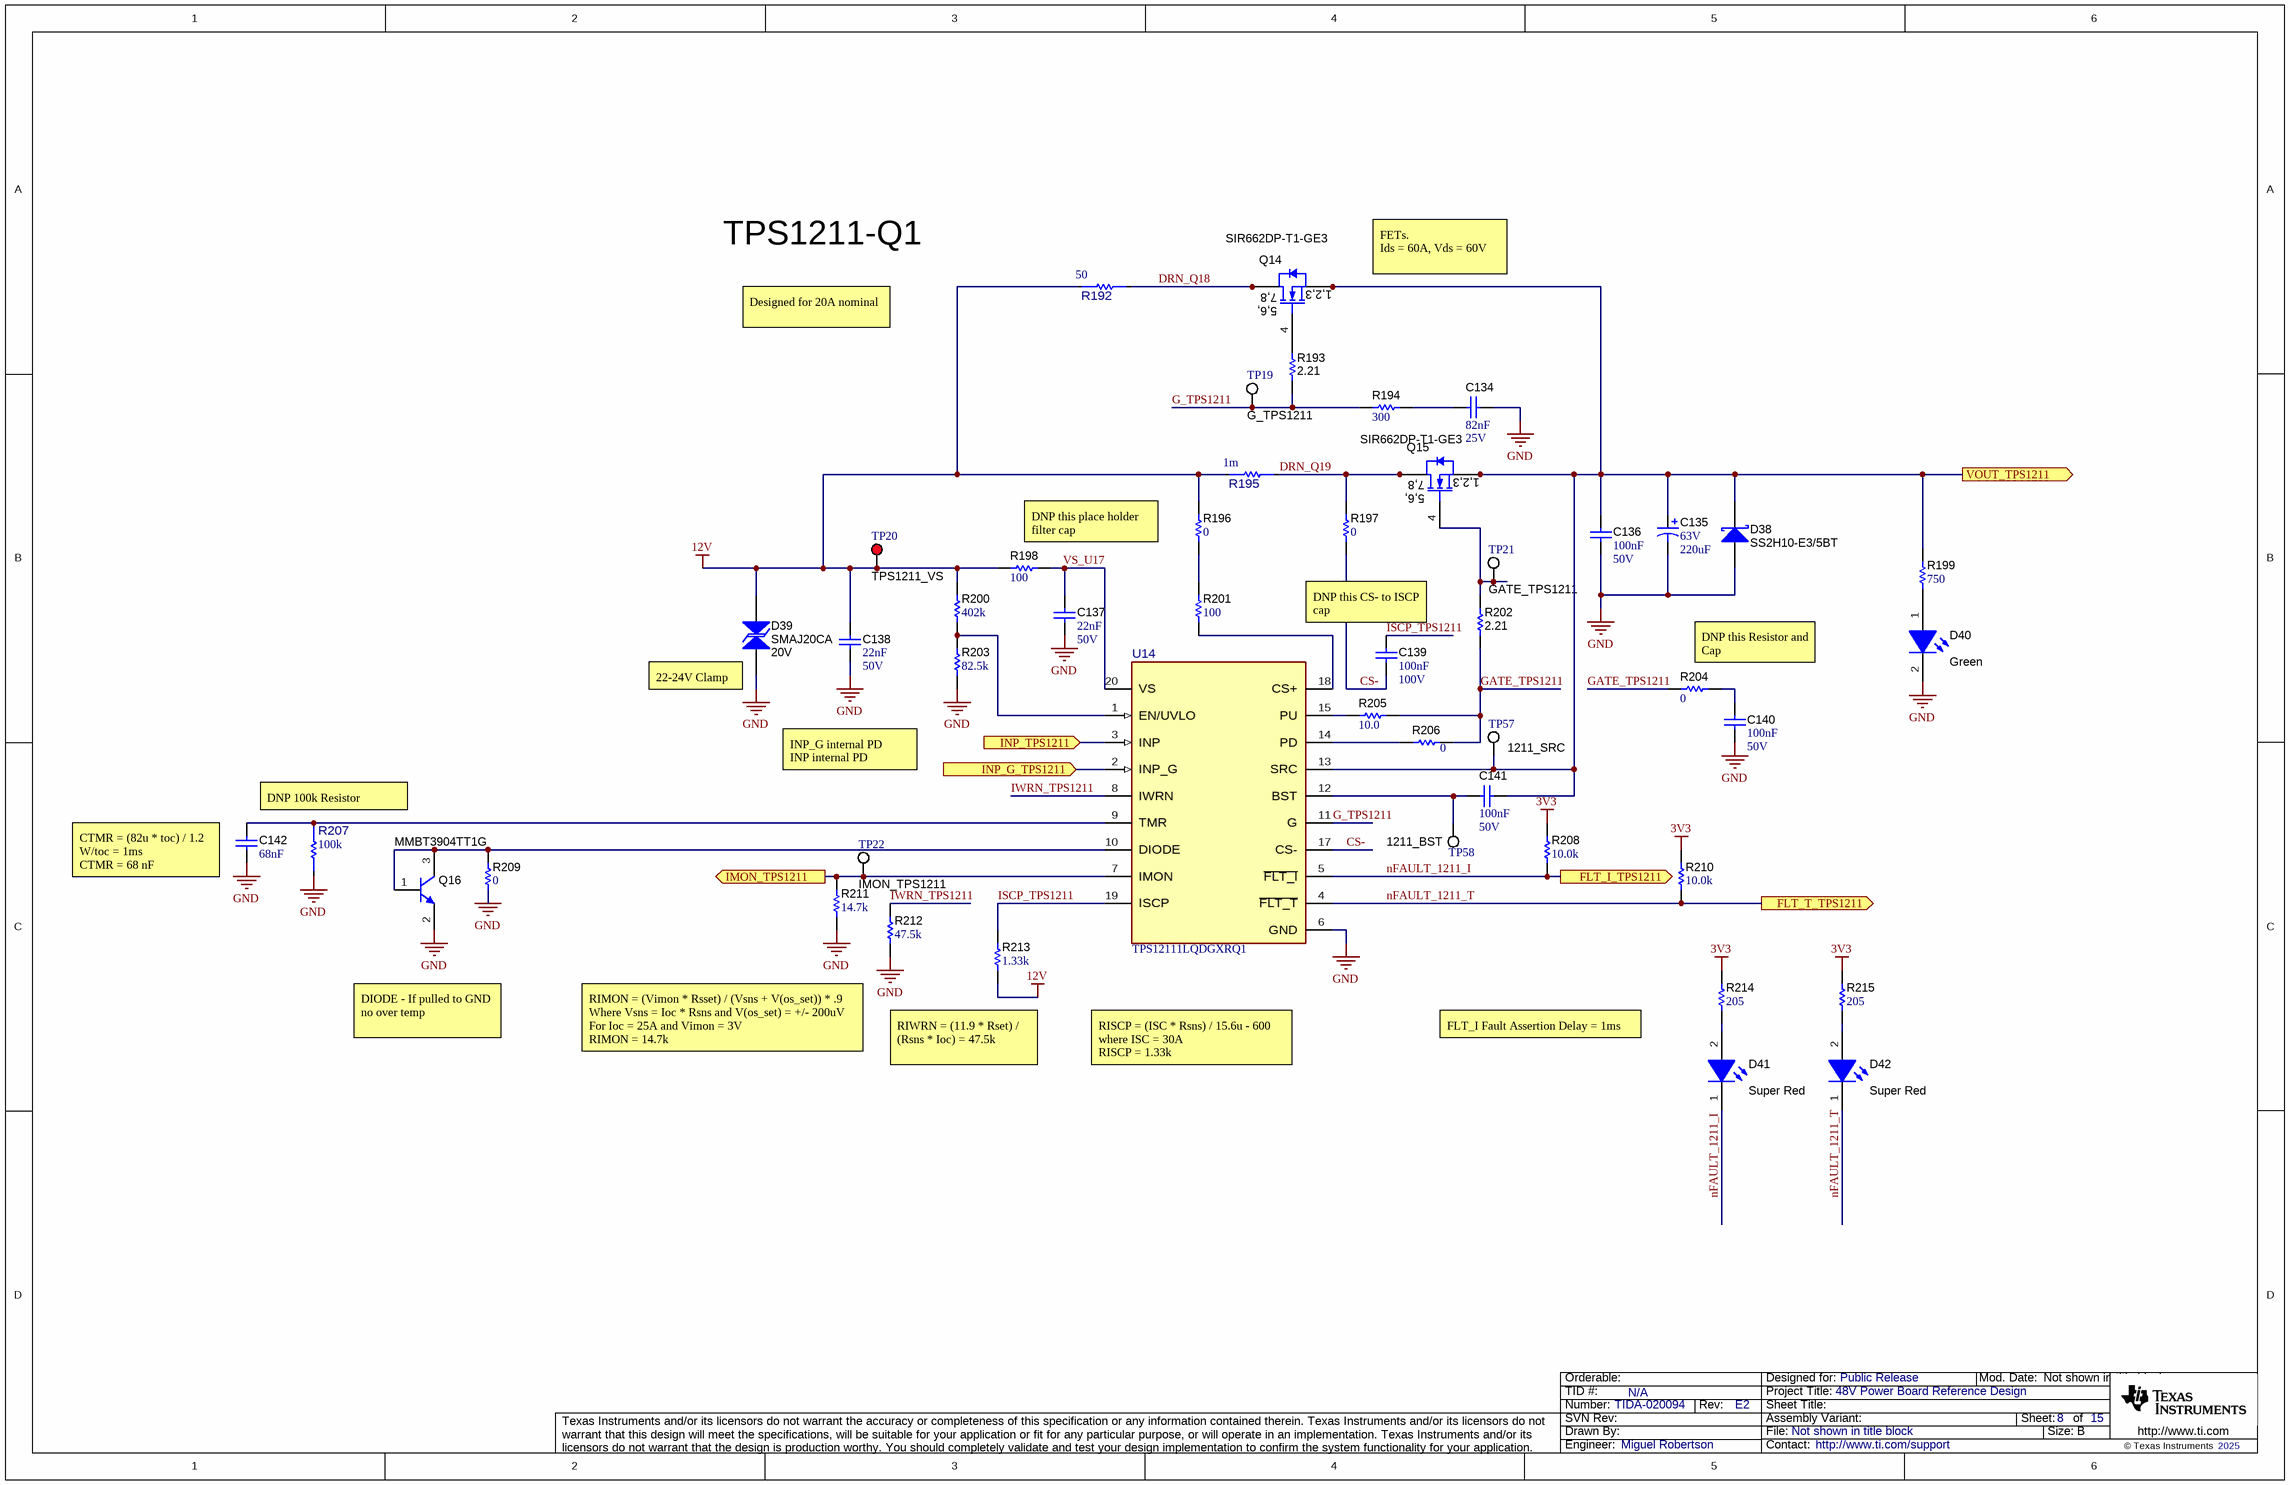
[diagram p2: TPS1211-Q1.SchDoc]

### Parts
C134  Cap_F: 82nF  VDC_V: 25V  [0603]  (hidden comment: GRM188R71E823KA01D)
C135  VDC_V: 63V  ValueDisplayed: 220uF  [AFK_1250x1350]  (hidden comment: AFK227M63H32T-F)
C136  Cap_F: 100nF  VDC_V: 50V  [0603]  (hidden comment: CGA3E2X7R1H104K080AA)
C137  Cap_F: 22nF  VDC_V: 50V  [0603]  (hidden comment: C0603C223K5RACTU)
C138  Cap_F: 22nF  VDC_V: 50V  [0603]  (hidden comment: C0603C223K5RACTU)
C139  Cap_F: 100nF  VDC_V: 100V  [0603]  (hidden comment: HMK107B7104KAHT)
C140  Cap_F: 100nF  VDC_V: 50V  [0603]  (hidden comment: 06035C104KAZ2A)
C141  Cap_F: 100nF  VDC_V: 50V  [0603]  (hidden comment: 06035C104KAZ2A)
C142  Cap_F: 68nF  [0603]  (hidden comment: 06035C104KAZ2A)
D38  SS2H10-E3/5BT  [SMB]
D39  SMAJ20CA  value 20V  [SMA_Bi]
D40  value Green  [LTST-C191_Green]  (hidden comment: LTST-C191KGKT)
D41  value Super Red  [WL-SMCW_RED]  (hidden comment: 150060SS75000)
D42  value Super Red  [WL-SMCW_RED]  (hidden comment: 150060SS75000)
Q14  SIR662DP-T1-GE3  [PowerPAK_SO-8]
Q15  SIR662DP-T1-GE3  [PowerPAK_SO-8]
Q16  MMBT3904TT1G  [SOT-416]
R192  value 50  [FP-ALN2512F50R0E-1_2512-MFG]  (hidden comment: ALN2512F50R0E-1)
R193  ValueDisplayed: 2.21  [0603]  (hidden comment: RC0603FR-072R21L)
R194  ValueDisplayed: 300  [0603]  (hidden comment: RC0603FR-07300RL)
R195  value 1m  [FP-ULRG32512R001FLFSLT_2512-MFG]  (hidden comment: ULRG32512R001FLFSLT)
R196  ValueDisplayed: 0  [0603]  (hidden comment: CRCW06030000Z0EA)
R197  ValueDisplayed: 0  [0603]  (hidden comment: CRCW06030000Z0EA)
R198  ValueDisplayed: 100  [0603]  (hidden comment: RC0603FR-07100RL)
R199  ValueDisplayed: 750  [0603]  (hidden comment: RC0603FR-07750RL)
R200  ValueDisplayed: 402k  [0603]  (hidden comment: RC0603FR-07402KL)
R201  ValueDisplayed: 100  [0603]  (hidden comment: CRCW060350R0FKEA)
R202  ValueDisplayed: 2.21  [0603]  (hidden comment: RC0603FR-072R21L)
R203  ValueDisplayed: 82.5k  [0603]  (hidden comment: RC0603FR-0782K5L)
R204  ValueDisplayed: 0  [0603]  (hidden comment: CRCW06030000Z0EA)
R205  ValueDisplayed: 10.0  [0603]  (hidden comment: RC0603FR-0710RL)
R206  ValueDisplayed: 0  [0603]  (hidden comment: CRCW06030000Z0EA)
R207  value 100k  [FP-ERJ-PB3B1003V_0603-IPC_A]  (hidden comment: ERJ-PB3B1003V)
R208  ValueDisplayed: 10.0k  [0603]  (hidden comment: ERJ-3EKF1002V)
R209  ValueDisplayed: 0  [0603]  (hidden comment: CRCW06030000Z0EA)
R210  ValueDisplayed: 10.0k  [0603]  (hidden comment: ERJ-3EKF1002V)
R211  ValueDisplayed: 14.7k  [0603]  (hidden comment: RC0603FR-0714K7L)
R212  ValueDisplayed: 47.5k  [0603]  (hidden comment: RC0603FR-0747K5L)
R213  ValueDisplayed: 1.33k  [0603]  (hidden comment: RC0603FR-071K33L)
R214  ValueDisplayed: 205  [0603]  (hidden comment: RC0603FR-07205RL)
R215  ValueDisplayed: 205  [0603]  (hidden comment: RC0603FR-07205RL)
TP19  G_TPS1211  [Keystone5012]
TP20  TPS1211_VS  [Keystone5010]
TP21  GATE_TPS1211  [Keystone5012]
TP22  IMON_TPS1211  [Keystone5012]
TP57  1211_SRC  [Keystone5012]
TP58  1211_BST  [Keystone5012]
U14  TPS12111LQDGXRQ1  [DGX0019A-MFG]

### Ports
FLT_I_TPS1211 (out), FLT_T_TPS1211 (out), IMON_TPS1211 (out), INP_G_TPS1211 (in), INP_TPS1211 (in), VOUT_TPS1211 (out)

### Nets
3V3: R208.1 R210.1 R214.2 R215.2
12V: C138.2 D39.2 R192.1 R195.1 R196.2 R198.1 R200.2 R213.1 TP20.1
GND: C134.1 C135.2(-) C136.2 C137.1 C138.1 C140.2 C142.2 D38.2(A) D39.1 D40.2(K) Q16.2(E) R203.1 R207.2 R209.1 R211.1 R212.1 U14.6(GND)
CS-: C139.2 R197.1 U14.17(CS-)  [project net CS-_8]
DRN_Q18: Q14.5(D) Q14.6(D) Q14.7(D) Q14.8(D) Q14.9(D) R192.2  [project net DRN_Q18_8]
DRN_Q19: Q15.5(D) Q15.6(D) Q15.7(D) Q15.8(D) Q15.9(D) R195.2 R197.2  [project net DRN_Q19_8]
G_TPS1211: R193.1 R194.1 TP19.1 U14.11(G)  [project net G_TPS1211_8]
GATE_TPS1211: R202.1 R204.2 R205.1 R206.1  [project net GATE_TPS1211_8]
IMON_TPS1211: R211.2 TP22.1 U14.7(IMON) ; port IMON_TPS1211
INP_G_TPS1211: U14.2(INP_G) ; port INP_G_TPS1211
INP_TPS1211: U14.3(INP) ; port INP_TPS1211
ISCP_TPS1211: C139.1 R213.2 U14.19(ISCP)  [project net ISCP_TPS1211_8]
IWRN_TPS1211: R212.2 U14.8(IWRN)  [project net IWRN_TPS1211_8]
nFAULT_1211_I: D41.1(K) R208.2 U14.5(~{FLT_I}) ; port FLT_I_TPS1211  [project net FLT_I_TPS1211]
nFAULT_1211_T: D42.1(K) R210.2 U14.4(~{FLT_T}) ; port FLT_T_TPS1211  [project net FLT_T_TPS1211]
VOUT_TPS1211: C135.1(+) C136.1 C141.1 D38.1(K) Q14.1(S) Q14.2(S) Q14.3(S) Q15.1(S) Q15.2(S) Q15.3(S) R199.2 TP57.1 U14.13(SRC) ; port VOUT_TPS1211
VS_U17: C137.2 R198.2 U14.20(VS)  [project net VS_U17_8]
NetC134_2: C134.2 R194.2
NetC140_1: C140.1 R204.1
NetC141_2: C141.2 TP58.1 U14.12(BST)
NetC142_1: C142.1 R207.1 U14.9(TMR)
NetD40_1: D40.1(A) R199.1
NetD41_2: D41.2(A) R214.1
NetD42_2: D42.2(A) R215.1
NetQ14_4: Q14.4(G) R193.2
NetQ15_4: Q15.4(G) R202.2 TP21.1
NetQ16_1: Q16.1(B) Q16.3(C) R209.2 U14.10(DIODE)
NetR196_1: R196.1 R201.1
NetR200_1: R200.1 R203.2 U14.1(EN/UVLO)
NetR201_2: R201.2 U14.18(CS+)
NetR205_2: R205.2 U14.15(PU)
NetR206_2: R206.2 U14.14(PD)

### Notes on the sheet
- TPS1211-Q1
- FETs.
  Ids = 60A, Vds = 60V
- Designed for 20A nominal
- DNP this place holder filter cap
- DNP this CS- to ISCP cap
- (near D39) 22-24V Clamp
- (near R204) DNP this Resistor and Cap
- INP_G internal PD
  INP internal PD
- DNP 100k Resistor
- (near C142) CTMR = (82u * toc) / 1.2 W/toc = 1ms                               CTMR = 68 nF
- DIODE - If pulled to GND no over temp
- FLT_I Fault Assertion Delay = 1ms
- RIMON = (Vimon * Rsset) / (Vsns + V(os_set)) * .9                     Where Vsns = Ioc * Rsns and V(os_set) = +/- 200uV                For Ioc = 25A and Vimon = 3V                           RIMON = 14.7k
- (near R213) RIWRN = (11.9 * Rset) / (Rsns * Ioc) = 47.5k
- RISCP = (ISC * Rsns) / 15.6u - 600                        where ISC = 30A                                   RISCP = 1.33k

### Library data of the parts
C134 = CMP-0007430-2: CAP, CERM, 0.082 uF, 25 V, +/- 10%, X7R, 0603; Manufacturer: MuRata; TaMin_C: -55°C; Polarized: N; SizeAreaWB_mm2: 4.68; Value1: Unknown; U/M: EA; TaMax_C: 125°C; SizeZ_mm: 1; SizeX_mm: 1.6; SizeY_mm: 0.8; SizeArea_mm2: 1.28; AEC Category: Q200
C135 = CMP-0011162-2: CAP, AL, 220 uF, 63 V, +/- 20%, 0.16 ohm, SMD; Manufacturer: Cornell Dubilier Electronics; TaMin_C: -55°C; ESR_ohm: 0.16; Polarized: Y; SizeAreaWB_mm2: 263.5; U/M: EA; Value: 220uF; TaMax_C: 105°C; SizeZ_mm: 14; SizeX_mm: 15; SizeY_mm: 13.5; Cap_Case: 12.5x13.5; SizeArea_mm2: 202.5; CompType: Capacitor; AEC Qualified: N; Cap_F: 220µF; IRMS_A: 800mA; AEC Category: Q200
C136 = CMP-0007078-1: CAP, CERM, 0.1 uF, 50 V, +/- 10%, X7R, AEC-Q200 Grade 1, 0603; Manufacturer: TDK; TaMin_C: -55°C; ESR_ohm: 29.6m; Polarized: N; SizeAreaWB_mm2: 4.68; Value1: 0.0296 ohm; U/M: EA; Value: 0.1uF; TaMax_C: 125°C; SizeZ_mm: 1; SizeX_mm: 1.6; SizeY_mm: 0.8; SizeArea_mm2: 1.28; AEC Qualified: Y; IRMS_A: 971.99mA; AEC Category: Q200
C137 C138 = CMP-0006901-3: CAP, CERM, 0.022 uF, 50 V, +/- 10%, X7R, 0603; Manufacturer: Kemet; TaMin_C: -55°C; Polarized: N; Value1: Unknown; U/M: EA; TaMax_C: 125°C; SizeAreaWB_mm2: 4.68; SizeZ_mm: 1; SizeX_mm: 1.6; SizeY_mm: 0.8; SizeArea_mm2: 1.28; AEC Category: Q200
C139 = CMP-0081011-1: CAP, CERM, 0.1 µF, 100 V,+/- 10%, X7R, AEC-Q200 Grade 1, 0603; Manufacturer: Taiyo Yuden; SizeAreaWB_mm2: 4.68; SizeArea_mm2: 1.28; AEC Qualified: Y; AEC Category: Q200; Value: 0.1uF; TaMax_C: 125°C; SizeZ_mm: 1; Polarized: N; TaMin_C: -55°C; SizeY_mm: 0.8; U/M: EA; SizeX_mm: 1.6; ValueDisplayed: 0.1µF
C140 C141 = CMP-0079095-1: CAP, CERM, 0.1 µF, 50 V,+/- 10%, X7R, AEC-Q200 Grade 1, 0603; Manufacturer: AVX; SizeAreaWB_mm2: 4.68; SizeArea_mm2: 1.28; AEC Qualified: Y; AEC Category: Q200; Value: 0.1uF; TaMax_C: 125°C; SizeZ_mm: 1; Polarized: N; TaMin_C: -55°C; SizeY_mm: 0.8; U/M: EA; SizeX_mm: 1.6; ValueDisplayed: 0.1µF
C142 = CMP-0079095-1: as C102 on sheet LM74900-Q1
D38 = CMP-0028987-2: Diode, Schottky, 100 V, 2 A, SMB; Manufacturer: Vishay-Semiconductor; Vf_V: 790mV; AEC Qualified: N; SizeArea_mm2: 21.336; Value: 100V; SizeX_mm: 5.6; Value1: 2A; Value2: 0.79V; SizeZ_mm: 2.6; SizeAreaWB_mm2: 44.156; AEC Category: Q101; TJmax_C: 175°C; SizeY_mm: 3.81
D39 = CMP-0085010-1: Diode, TVS, Bi, 20 V, 32.4 Vc, 400 W, 12.3 A, SMA (non-polarized); Manufacturer: Littelfuse; SizeZ_mm: 2.65; Ppk: 400W; Vbr_Min: 22.2V; SizeX_mm: 5.075; Ipp: 12.3A; Value1: 32.4V; AEC Qualified: N; RJA_CperW: 120; Vbr_Max: 24.5V; SizeY_mm: 2.575; SizeAreaWB_mm2: 32.368125; SizeArea_mm2: 13.068125; AEC Category: Q101
D40 = CMP-0078478-1: as D27 on sheet LM74900-Q1
D41 D42 = CMP-0002893-1: LED, Super Red, SMD; Manufacturer: Wurth Elektronik; Io_A: 20mA; Value1: W; U/M: EA; Vf_V: 1.9V; Type: AlInGaP
Q14 Q15 = CMP-0000870-1: MOSFET, N-CH, 60 V, 60 A, PowerPAK SO-8; Alternate Manufacturer: None; Manufacturer: Vishay-Semiconductor; SizeZ_mm: 1.12; ChType: N; Value2: 96 nC; Value1: 0.002; VdsMax_V: 60V; SizeX_mm: 5.99; SizeY_mm: 4.9; Vgs_V: 2.5V; Value: 60V; Rdson45_ohm: 2.7m; SizeArea_mm2: 29.351; AEC Category: Q101; IdsMax_A: 60A; SizeAreaWB_mm2: 55.131; U/M: EA; QgTyp_nC: 96
Q16 = CMP-0000428-2: Transistor, NPN, 40 V, 0.2 A, SOT-416; Manufacturer: ON Semiconductor; TaMax_C: 150°C; Value2: 300; Value1: 0.2 A; Vcesat1_V: 300mV; SizeX_mm: 1.6; TaMin_C: -55°C; IcRated_A: 200mA; CompType: BJT; SizeZ_mm: 0.95; Value: 40 V; SizeArea_mm2: 2.56; NPN: 1; Vceo_V: 40V; PNP: 0; AEC Category: Q101; SizeAreaWB_mm2: 6.76; U/M: EA
R192 = CMP-0096129-1: 50 Ohms ±1% 3.5W Chip Resistor 2512 (6432 Metric) Thick Film; Manufacturer: Ohmite; SizeZ_mm: 0.64mm; VDC_V: 200V; AEC Qualified: No; TempCo: 150ppm/°C
R193 R202 = CMP-0023007-4: RES, 2.21, 1%, 0.1 W, 0603; Manufacturer: Yageo; Power_W: 100mW; TempCo: 200 ppm/C; Value_Code: 2R21; Value: 2.21; EIA_Code: E96; SizeX_mm: 1.6; SizeY_mm: 0.8; SizeZ_mm: 1; Value2: 0.1W; SizeArea_mm2: 1.28; AEC Qualified: N; VDC_V: 75V; AEC Category: Q200; SizeAreaWB_mm2: 4.68
R194 = CMP-0023013-5: RES, 300, 1%, 0.1 W, 0603; Manufacturer: Yageo; Power_W: 100mW; TempCo: 100 ppm/C; Value_Code: 300R; Value: 300; SizeX_mm: 1.6; SizeY_mm: 0.8; SizeZ_mm: 1; Value2: 0.1W; SizeArea_mm2: 1.28; AEC Qualified: N; VDC_V: 75V; AEC Category: Q200; SizeAreaWB_mm2: 4.68
R195 = CMP-0042666-1: Res Metal Strip 2512 0.001 Ohm 1% 3W ±50ppm/C Pad SMD Automotive T/R; Manufacturer: TT Electronics; AEC Grade: Grade 0; AEC Qualified: Yes; SizeZ_mm: 0.8mm; TempCo: 50ppm/°C; TaMax_C: +170°C; TaMin_C: -55°C
R196 R197 R204 R206 R209 = CMP-0025697-4: as R117 on sheet LM74900-Q1
R198 = CMP-0022736-4: RES, 100, 1%, 0.1 W, 0603; Manufacturer: Yageo; Power_W: 100mW; TempCo: 100 ppm/C; Value_Code: 100R; Value: 100; EIA_Code: E96; SizeX_mm: 1.6; SizeY_mm: 0.8; SizeZ_mm: 1; Value2: 0.1W; SizeArea_mm2: 1.28; AEC Qualified: N; VDC_V: 75V; AEC Category: Q200; SizeAreaWB_mm2: 4.68
R199 = CMP-0023266-5: as R116 on sheet LM74900-Q1
R200 = CMP-0023096-4: RES, 402 k, 1%, 0.1 W, 0603; Manufacturer: Yageo; Power_W: 100mW; TempCo: 100 ppm/C; Value: 402k; EIA_Code: E96; SizeX_mm: 1.6; SizeY_mm: 0.8; SizeZ_mm: 1; Value2: 0.1W; SizeArea_mm2: 1.28; AEC Qualified: N; VDC_V: 75V; AEC Category: Q200; SizeAreaWB_mm2: 4.68
R201 = CMP-0022479-2: RES, 50, 1%, 0.1 W, 0603; Manufacturer: Vishay-Dale; Power_W: 100mW; TempCo: 100 ppm/C; Value_Code: 50R0; U/M: EA; Value: 50; SizeX_mm: 1.6; SizeY_mm: 0.8; SizeZ_mm: 1; Value2: 0.1W; SizeArea_mm2: 1.28; VDC_V: 75V; AEC Category: Q200
R203 = CMP-0023291-5: RES, 82.5 k, 1%, 0.1 W, 0603; Manufacturer: Yageo; Power_W: 100mW; TempCo: 100 ppm/C; Value_Code: 82k5; Value: 82.5k; EIA_Code: E96; SizeX_mm: 1.6; SizeY_mm: 0.8; SizeZ_mm: 1; Value2: 0.1W; SizeArea_mm2: 1.28; AEC Qualified: N; VDC_V: 75V; AEC Category: Q200; SizeAreaWB_mm2: 4.68
R205 = CMP-0022751-4: RES, 10.0, 1%, 0.1 W, 0603; Manufacturer: Yageo; Power_W: 100mW; TempCo: 100 ppm/C; Value_Code: 10R0; Value: 10.0; EIA_Code: E96; Res_ohm: 10; SizeX_mm: 1.6; SizeY_mm: 0.8; SizeZ_mm: 1; Value2: 0.1W; SizeArea_mm2: 1.28; AEC Qualified: N; VDC_V: 75V; AEC Category: Q200; SizeAreaWB_mm2: 4.68
R207 = CMP-0092407-1: as R120 on sheet LM74900-Q1
R208 R210 = CMP-0022684-3: as R123 on sheet LM74900-Q1
R211 = CMP-0022803-5: RES, 14.7 k, 1%, 0.1 W, 0603; Manufacturer: Yageo; Power_W: 100mW; TempCo: 100 ppm/C; Value_Code: 14k7; Value: 14.7k; EIA_Code: E96; SizeX_mm: 1.6; SizeY_mm: 0.8; SizeZ_mm: 1; Value2: 0.1W; SizeArea_mm2: 1.28; AEC Qualified: N; VDC_V: 75V; AEC Category: Q200; SizeAreaWB_mm2: 4.68
R212 = CMP-0023132-5: RES, 47.5 k, 1%, 0.1 W, 0603; Manufacturer: Yageo; Power_W: 100mW; TempCo: 100 ppm/C; Value_Code: 47k5; Value: 47.5k; EIA_Code: E96; SizeX_mm: 1.6; SizeY_mm: 0.8; SizeZ_mm: 1; Value2: 0.1W; SizeArea_mm2: 1.28; AEC Qualified: N; VDC_V: 75V; AEC Category: Q200; SizeAreaWB_mm2: 4.68
R213 = CMP-0022875-5: RES, 1.33 k, 1%, 0.1 W, 0603; Manufacturer: Yageo; Power_W: 100mW; TempCo: 100 ppm/C; Value_Code: 1k33; Value: 1.33k; EIA_Code: E96; SizeX_mm: 1.6; SizeY_mm: 0.8; SizeZ_mm: 1; Value2: 0.1W; SizeArea_mm2: 1.28; AEC Qualified: N; VDC_V: 75V; AEC Category: Q200; SizeAreaWB_mm2: 4.68
R214 R215 = CMP-0022904-5: RES, 205, 1%, 0.1 W, 0603; Manufacturer: Yageo; Power_W: 100mW; TempCo: 100 ppm/C; Value_Code: 205R; Value: 205; EIA_Code: E96; SizeX_mm: 1.6; SizeY_mm: 0.8; SizeZ_mm: 1; Value2: 0.1W; SizeArea_mm2: 1.28; AEC Qualified: N; VDC_V: 75V; AEC Category: Q200; SizeAreaWB_mm2: 4.68
TP19 TP21 TP22 TP57 TP58 = CMP-0055149-1: as TP11 on sheet LM74900-Q1
TP20 = CMP-0055147-2: as TP9 on sheet LM74900-Q1
U14 = CMP-0124514-1: Automotive 3.5-V to 40-V high-side driver with protection and diagnostics 19-VSSOP -40 to 125; Manufacturer: Texas Instruments; SizeZ_mm: 1.1mm; AEC Qualified: Yes; AEC Grade: Grade 1; Max Supply Voltage: 40V; Min Supply Voltage: 3.5V; Nominal Supply Current: 613uA; Number Of Outputs: 1; Standoff Height: 0.05mm; TaMax_C: +125°C; TaMin_C: -40°C; TJmax_C: +150°C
